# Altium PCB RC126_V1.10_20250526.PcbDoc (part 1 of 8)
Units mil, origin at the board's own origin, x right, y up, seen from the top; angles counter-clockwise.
Board outline 6299.62 x 3544.12 mil, 4 copper layers (Top, GND, Power, Bottom), stack 35.4 mil thick; 509 components, 417 nets, 1867 pads, 2150 vias.
Unrouted connection lines stored in the file: 1451.
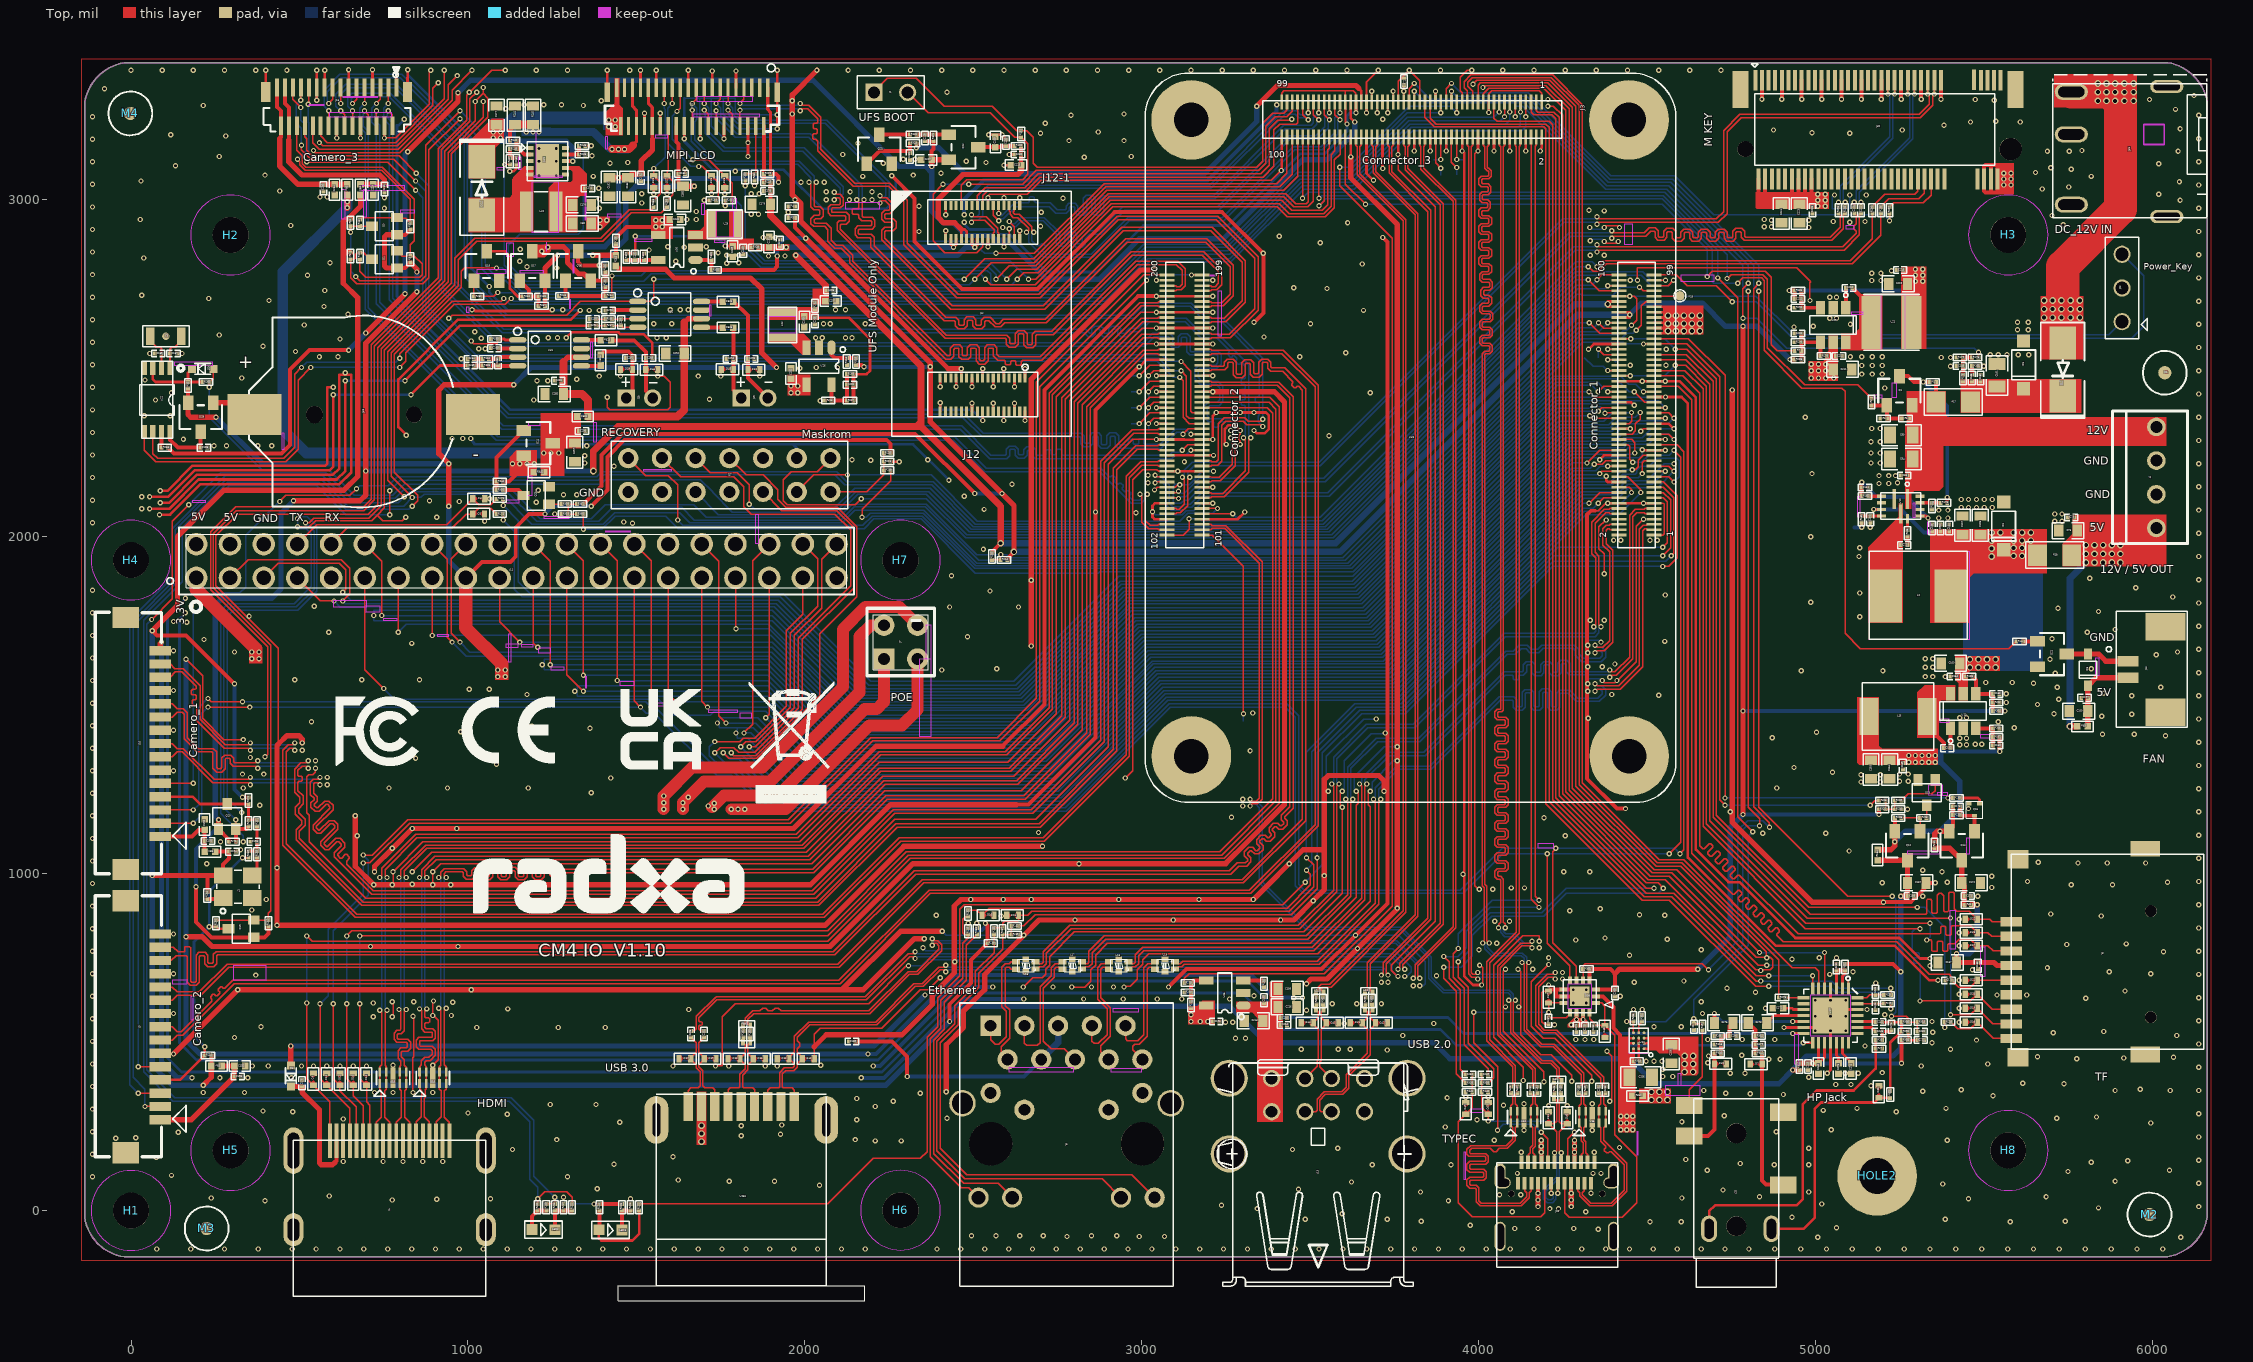
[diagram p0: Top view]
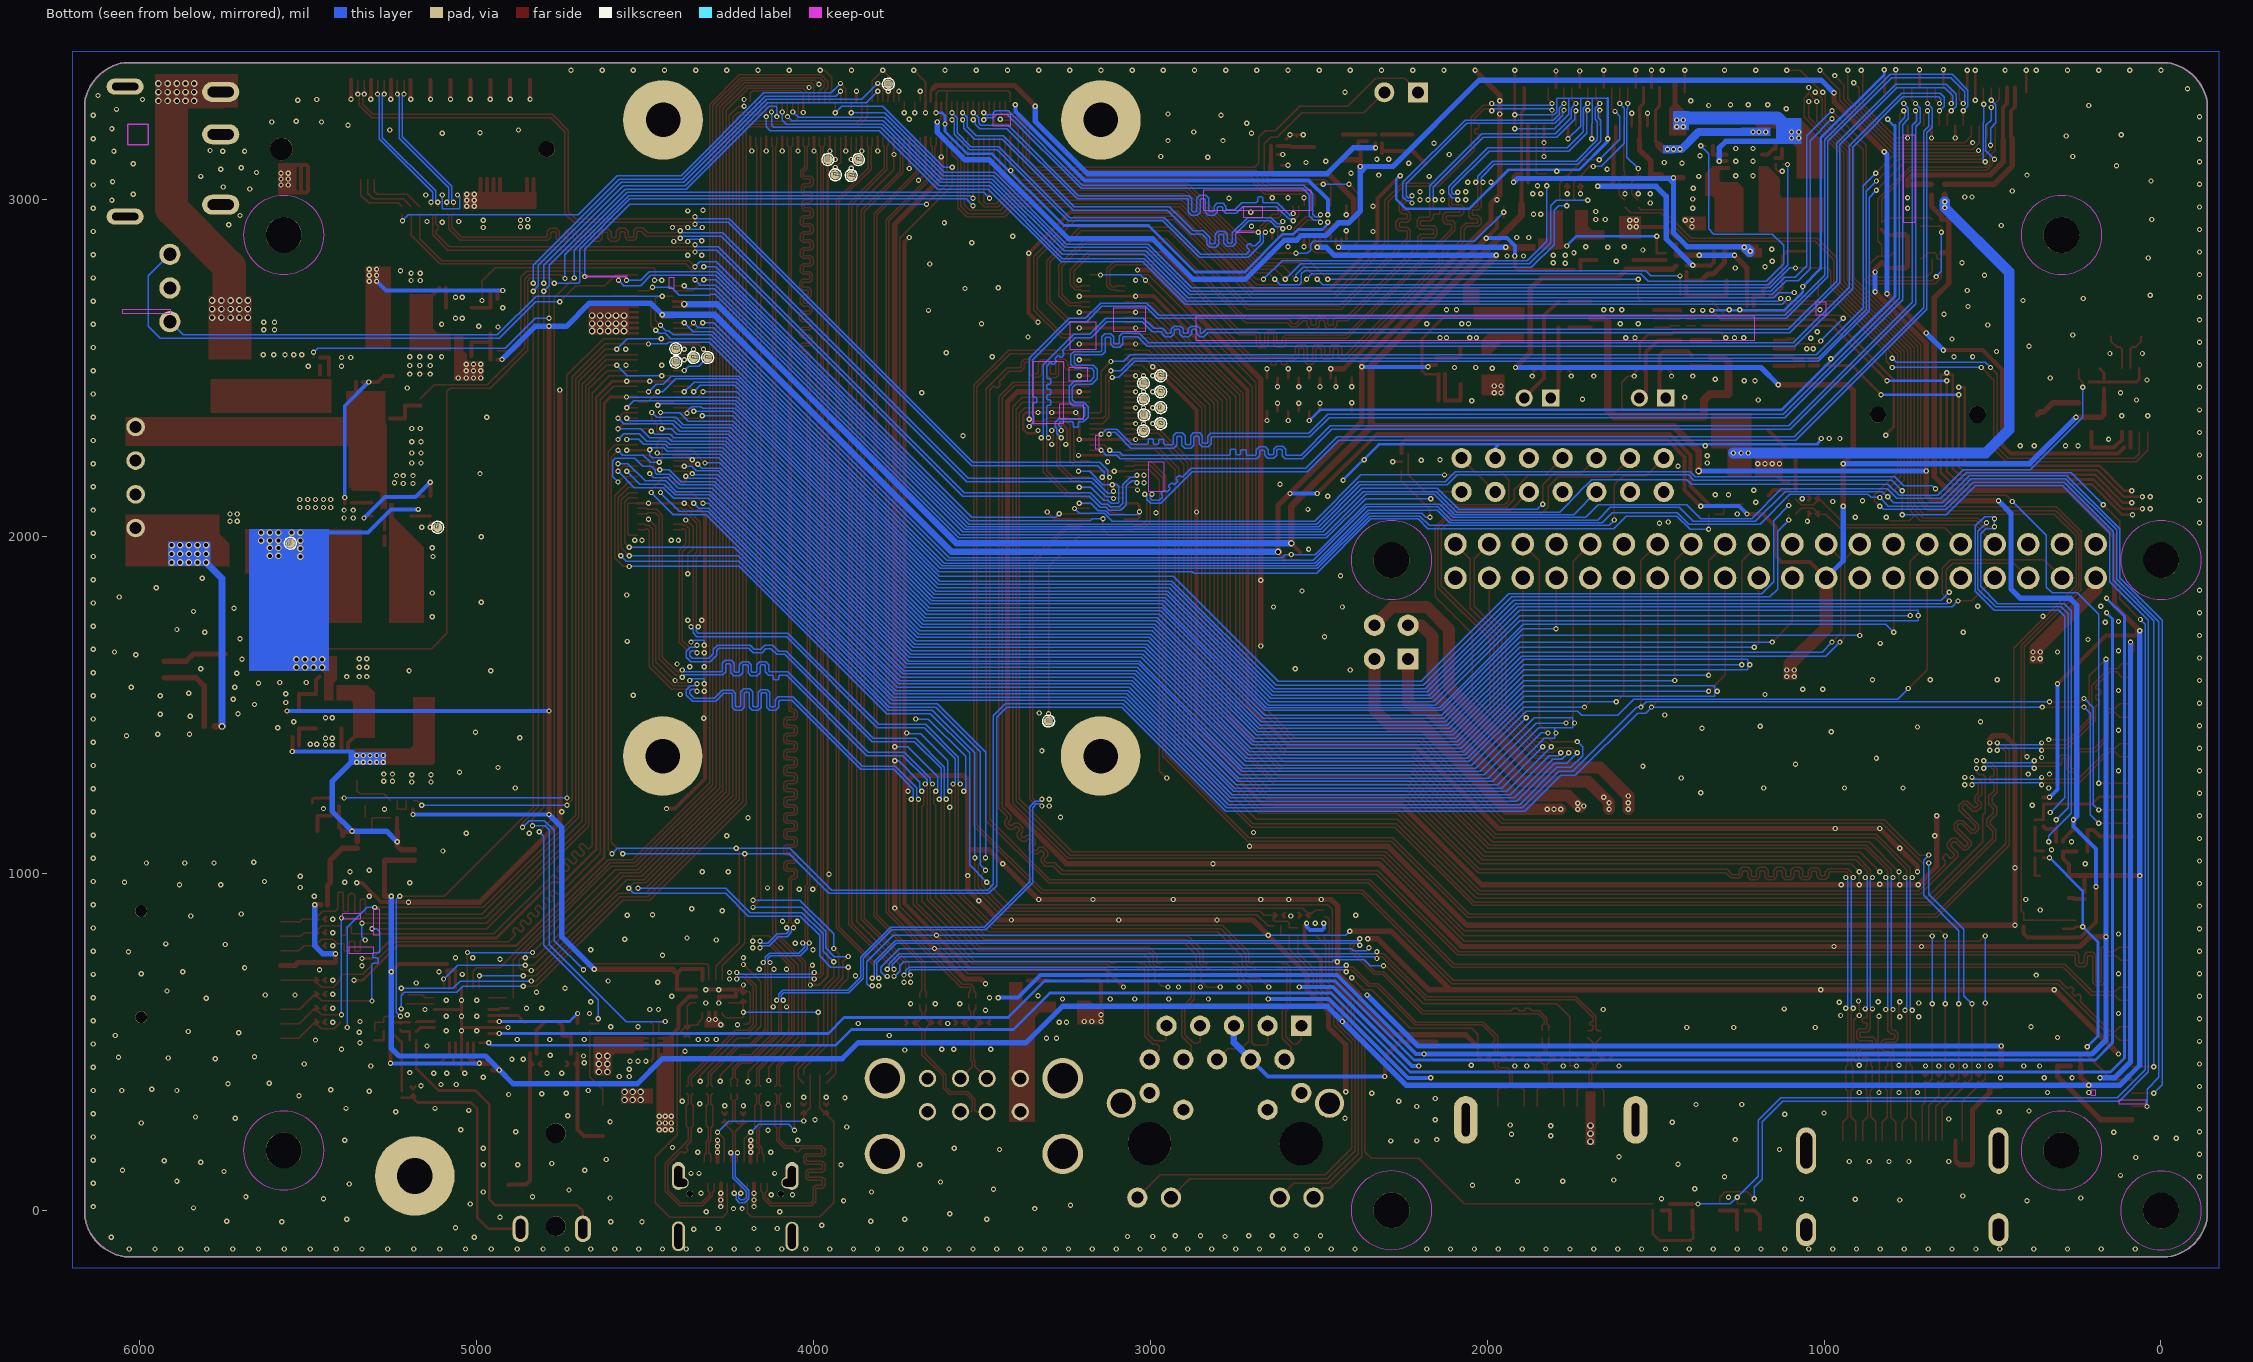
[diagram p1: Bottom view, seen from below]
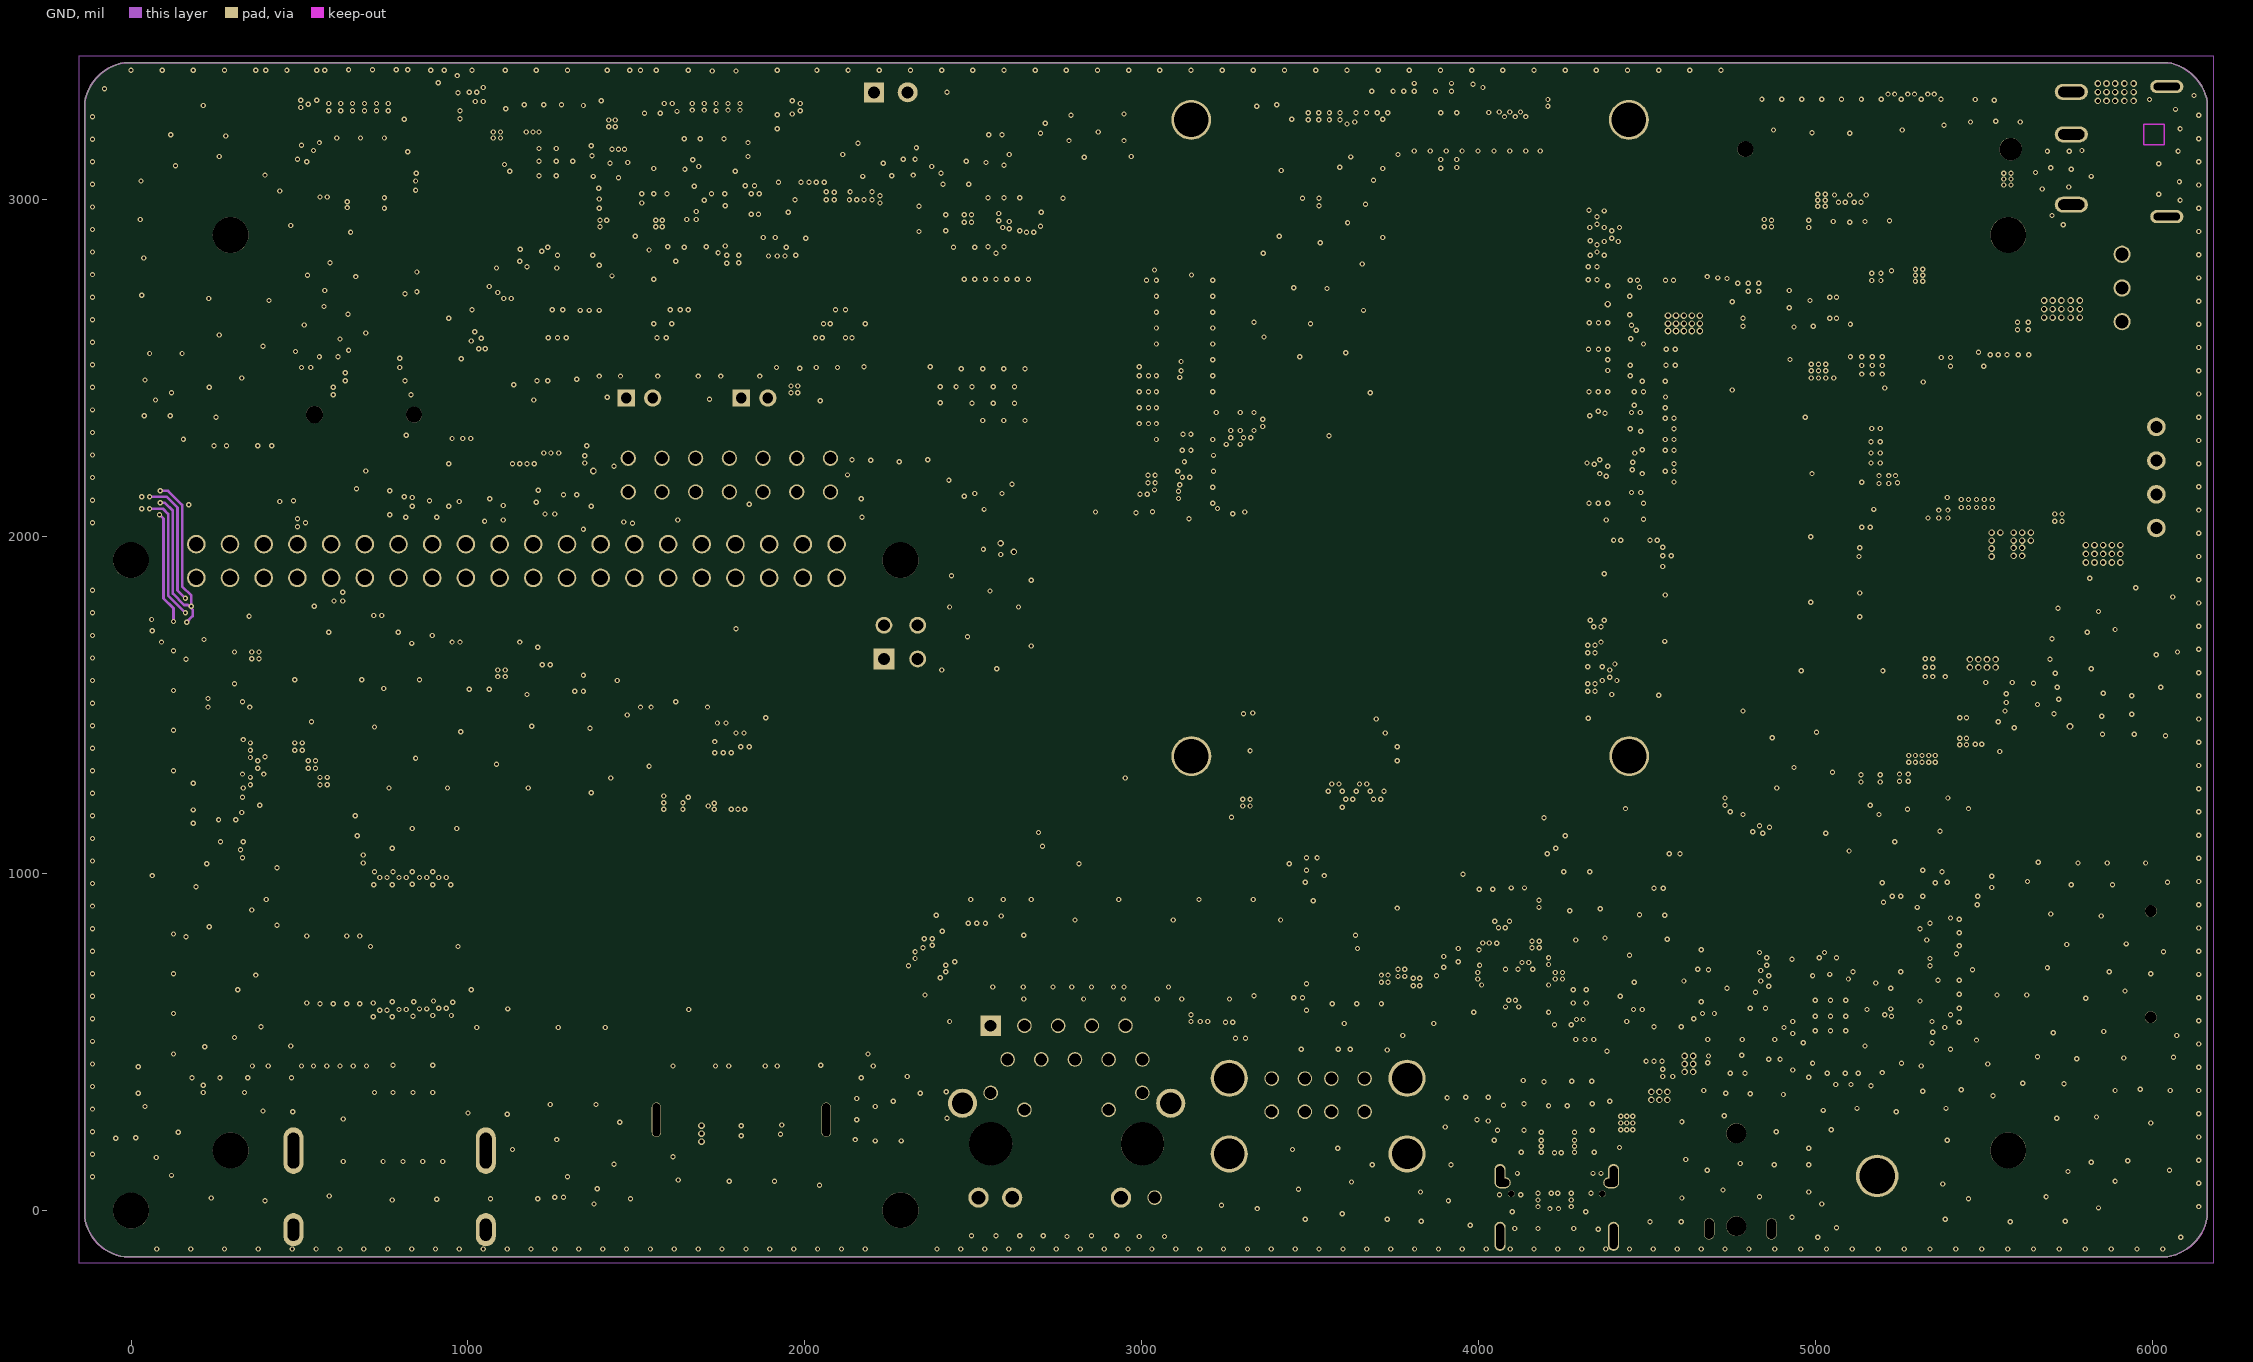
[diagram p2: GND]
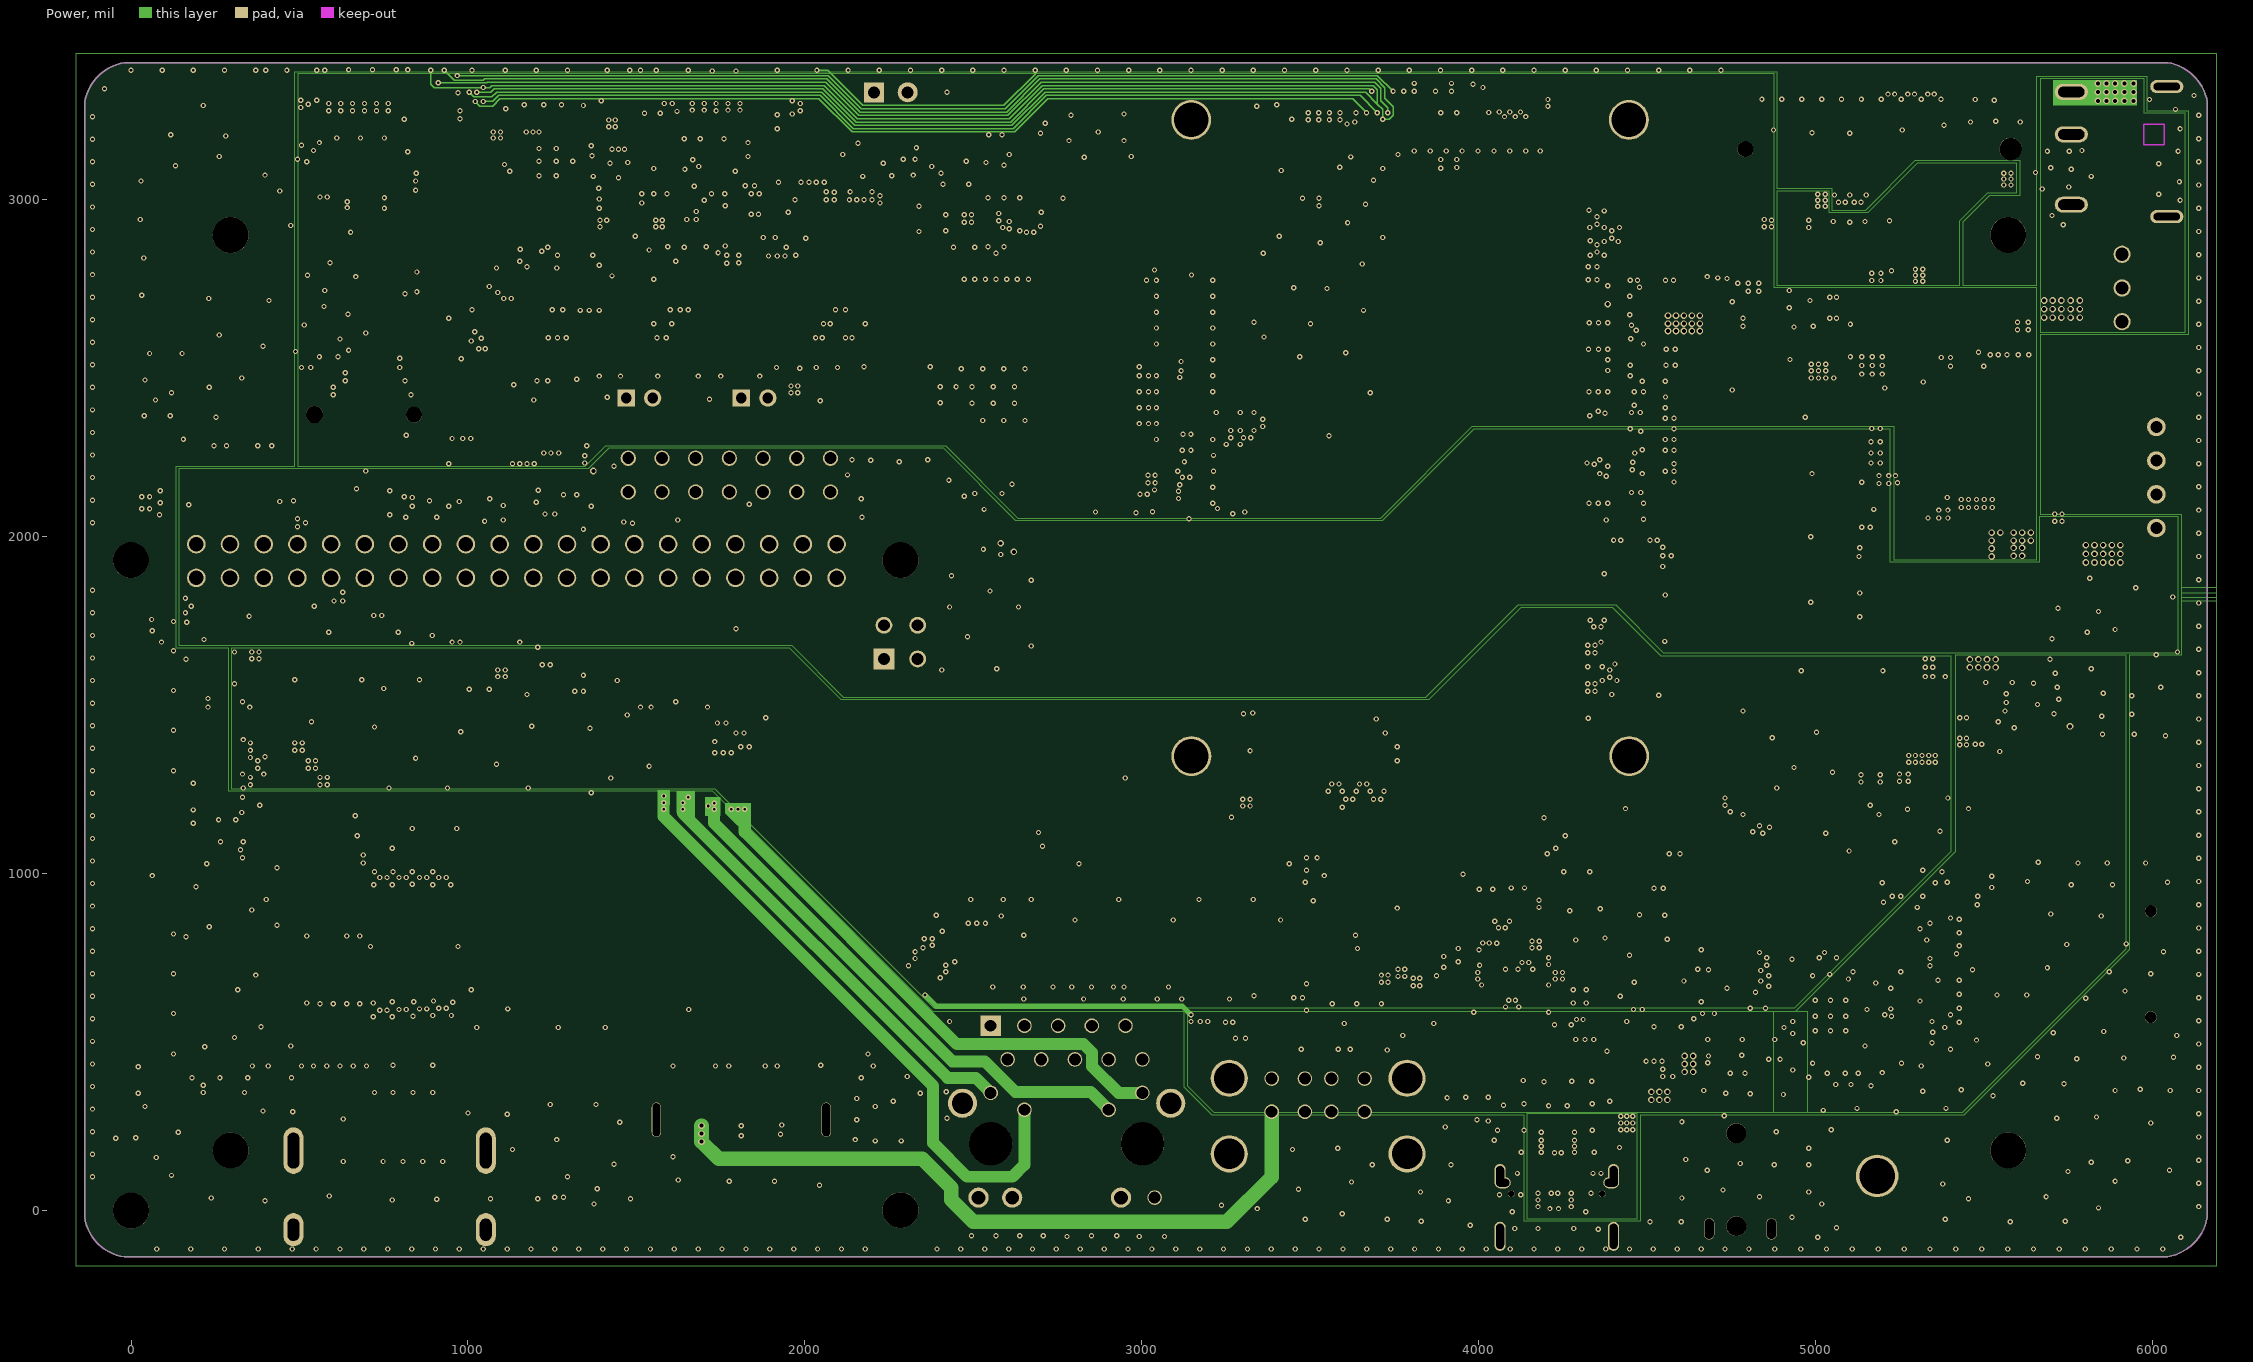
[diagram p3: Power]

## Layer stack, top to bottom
Solder Mask Top: solder mask 0.4, Solder Resist, Dk 3.5
Top: signal copper 1.35
Dielectric 1: dielectric 10, FR-4, Dk 4.3
GND: signal copper 1.35
Dielectric2: dielectric 10, FR-4, Dk 4.3
Power: signal copper 1.35
Dielectric3: dielectric 10, FR-4, Dk 4.3
Bottom: signal copper 1.35
Solder Mask Bottom: solder mask 0.4, Solder Resist, Dk 3.5

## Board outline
-137.8,3288.58 -137.79,3288.63 cw(c4.92,3263.98) -19.69,3406.69 6043.7,3406.69 6043.62,3406.71 cw(c6020.78,3265.66) 6161.81,3288.58 6161.81,-19.29 6161.82,-19.26 cw(c6017.43,6.98) 6043.7,-137.4 -19.69,-137.4 -19.63,-137.41 cw(c-0.02,0.38) -137.8,-19.29

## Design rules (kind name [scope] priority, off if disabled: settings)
Clearance "Clearance - Default - DEFAULT - Via" [IsVia vs IsVia] p1: gap=0 ignorepadtopadclearanceinfootprint=FALSE
Clearance "Clearance - Default - DEFAULT- SMD" [IsVia vs IsSMTPin] p2: gap=0 ignorepadtopadclearanceinfootprint=FALSE
Clearance "Clearance - Default - DEFAULT - Net" [All] p3: gap=3.94 ignorepadtopadclearanceinfootprint=FALSE except(7.87: Arc-Fill Arc-Poly Arc-Region Track-Fill Track-Poly Track-Region SMDPad-Fill SMDPad-Poly SMDPad-Region THPad-Fill THPad-Poly THPad-Region Via-Fill Via-Poly Via-Region Fill-Fill Fill-Poly Fill-Region Poly-Poly Poly-Region Region-Region; 10: Arc-Hole Track-Hole SMDPad-Hole THPad-Hole Via-Hole Fill-Hole Poly-Hole Region-Hole Text-Text Text-Hole)
ComponentClearance "ComponentClearance - Default - DEFAULT" [All] p1: gap=0 collisioncheckmode=3 verticalgap=10 showdistances=FALSE
DiffPairsRouting "DiffPairsRouting - DiffPair - SSTX2" [InDifferentialPairClass('DiffPairClassFor_DP_GAP_39370_Width_39370')] p1: maxlimit=3.94 minlimit=3.94 mostfreqgap=3.94 toplayer_minwidth=3.94 toplayer_maxwidth=3.94 toplayer_prefwidth=3.94 midlayer1_minwidth=3.94 midlayer1_maxwidth=3.94 midlayer1_prefwidth=3.94 midlayer2_minwidth=3.94 midlayer2_maxwidth=3.94 midlayer2_prefwidth=3.94 bottomlayer_minwidth=3.94 bottomlayer_maxwidth=3.94 bottomlayer_prefwidth=3.94 maxuncoupledlength=500
DiffPairsRouting "DiffPairsRouting - DiffPair - Default" [All] p2: maxlimit=5.91 minlimit=5.91 mostfreqgap=5.91 toplayer_minwidth=3.94 toplayer_maxwidth=3.94 toplayer_prefwidth=3.94 midlayer1_minwidth=3.94 midlayer1_maxwidth=3.94 midlayer1_prefwidth=3.94 midlayer2_minwidth=3.94 midlayer2_maxwidth=3.94 midlayer2_prefwidth=3.94 bottomlayer_minwidth=3.94 bottomlayer_maxwidth=3.94 bottomlayer_prefwidth=3.94 maxuncoupledlength=500
FanoutControl Fanout_SOIC [IsSOIC] p1: bgadir=Out bgaviamode=Centered fanoutstyle=Auto fanoutdirection=Alternating viagrid=1 // Fanout_SOIC (Default Rule)
FanoutControl Fanout_Small [(CompPinCount < 5)] p2: bgadir=Out bgaviamode=Centered fanoutstyle=Auto fanoutdirection=OutThenIn viagrid=1 // Fanout_Small (Default Rule)
FanoutControl Fanout_LCC [IsLCC] p3: bgadir=Out bgaviamode=Centered fanoutstyle=Auto fanoutdirection=Alternating viagrid=1 // Fanout_LCC (Default Rule)
FanoutControl Fanout_BGA [IsBGA] p4: bgadir=Out bgaviamode=Centered fanoutstyle=Auto fanoutdirection=Alternating viagrid=1 // Fanout_BGA (Default Rule)
HoleToHoleClearance "HoleToHoleClearance - Default - DEFAULT" [All] p1: gap=0 allowstackedmicrovias=TRUE
Length "Length - DiffPair - Default" [InAnyDifferentialPair] p1: maxlimit=18503.27 minlimit=0
Length "Length - NetClass - HighSpeedClass_4(RuleSet)" [InNetClass('HighSpeedClass_4(RuleSet)')] p2: maxlimit=18503.27 minlimit=0
Length "Length - NetClass - MLNetGroup16" [InNetClass('MLNetGroup16')] p3: maxlimit=18503.27 minlimit=0
Length "Length - NetClass - MLNetGroup11" [InNetClass('MLNetGroup11')] p4: maxlimit=18503.27 minlimit=0
Length "Length - NetClass - MLNetGroup14" [InNetClass('MLNetGroup14')] p5: maxlimit=18503.27 minlimit=0
Length "Length - NetClass - MLNetGroup1" [InNetClass('MLNetGroup1')] p6: maxlimit=18503.27 minlimit=0
Length "Length - NetClass - MLNetGroup15" [InNetClass('MLNetGroup15')] p7: maxlimit=18503.27 minlimit=0
Length "Length - NetClass - MLNetGroup12" [InNetClass('MLNetGroup12')] p8: maxlimit=18503.27 minlimit=0
Length "Length - NetClass - MLNetGroup10" [InNetClass('MLNetGroup10')] p9: maxlimit=18503.27 minlimit=0
Length "Length - NetClass - MLNetGroup13" [InNetClass('MLNetGroup13')] p10: maxlimit=18503.27 minlimit=0
Length "Default Length_1" [All] p11: maxlimit=50000 minlimit=0
Length "Default Length" [All] p12: maxlimit=18503.27 minlimit=0
MatchedLengths "MatchedLengths - DiffPair - Default" [InAnyDifferentialPair] p1: tolerance=19.68 checknetsindiffpair=TRUE checkdiffpairvsdiffpair=FALSE checkxsignals=FALSE checkothers=FALSE
MatchedLengths "MatchedLengths - NetClass - HighSpeedClass_4(RuleSet)" [InNetClass('HighSpeedClass_4(RuleSet)')] p2: tolerance=19.68 checknetsindiffpair=FALSE checkdiffpairvsdiffpair=TRUE checkxsignals=TRUE checkothers=TRUE
MatchedLengths "MatchedLengths - NetClass - MLNetGroup11" [InNetClass('MLNetGroup11')] p3: tolerance=19.68 checknetsindiffpair=FALSE checkdiffpairvsdiffpair=TRUE checkxsignals=TRUE checkothers=TRUE
MatchedLengths "MatchedLengths - NetClass - MLNetGroup16" [InNetClass('MLNetGroup16')] p4: tolerance=19.68 checknetsindiffpair=FALSE checkdiffpairvsdiffpair=TRUE checkxsignals=TRUE checkothers=TRUE
MatchedLengths "MatchedLengths - NetClass - MLNetGroup14" [InNetClass('MLNetGroup14')] p5: tolerance=19.68 checknetsindiffpair=FALSE checkdiffpairvsdiffpair=TRUE checkxsignals=TRUE checkothers=TRUE
MatchedLengths "MatchedLengths - NetClass - MLNetGroup1" [InNetClass('MLNetGroup1')] p6: tolerance=19.68 checknetsindiffpair=FALSE checkdiffpairvsdiffpair=TRUE checkxsignals=TRUE checkothers=TRUE
MatchedLengths "MatchedLengths - NetClass - MLNetGroup15" [InNetClass('MLNetGroup15')] p7: tolerance=19.68 checknetsindiffpair=FALSE checkdiffpairvsdiffpair=TRUE checkxsignals=TRUE checkothers=TRUE
MatchedLengths "MatchedLengths - NetClass - MLNetGroup13" [InNetClass('MLNetGroup13')] p8: tolerance=19.68 checknetsindiffpair=FALSE checkdiffpairvsdiffpair=TRUE checkxsignals=TRUE checkothers=TRUE
MatchedLengths "MatchedLengths - NetClass - MLNetGroup12" [InNetClass('MLNetGroup12')] p9: tolerance=19.68 checknetsindiffpair=FALSE checkdiffpairvsdiffpair=TRUE checkxsignals=TRUE checkothers=TRUE
MatchedLengths "MatchedLengths - NetClass - MLNetGroup10" [InNetClass('MLNetGroup10')] p10: tolerance=19.68 checknetsindiffpair=FALSE checkdiffpairvsdiffpair=TRUE checkxsignals=TRUE checkothers=TRUE
MatchedLengths "Default Matched Lengths" [All] p11: tolerance=19.68 checknetsindiffpair=FALSE checkdiffpairvsdiffpair=TRUE checkxsignals=TRUE checkothers=TRUE
MaxMinImpedance "Default Impedance" [All] p1: minimum=50.00 maximum=150.0
MaxMinImpedance "Default Impedance_1" [All] p2: minimum=50.00 maximum=150.0
ParallelSegment "Default Parallel Segment Same Layer_1" [All] p1: limit=1000 gap=200
ParallelSegment "Default Parallel Segment Adjasent_1" [All] p2: limit=1000 gap=200
ParallelSegment "Default Parallel Segment Same Layer" [All] p3: limit=1000 gap=200
ParallelSegment "Default Parallel Segment Adjasent" [All] p4: limit=1000 gap=200
PlaneClearance "PlaneClearance - FootPrint 'CON_TH20X2_2D54_STA'" [HasFootprint('CON_TH20X2_2D54_STA')] p1: clearance=7.87 // PAD - Power Plane Clearance
PlaneClearance "PlaneClearance - FootPrint 'CONM_TH2X2_2D54_STA'" [HasFootprint('CONM_TH2X2_2D54_STA')] p2: clearance=7.5 // PAD - Power Plane Clearance
PlaneClearance "PlaneClearance - FootPrint 'M2-M_KEY_SM_75_0D5'" [HasFootprint('M2-M_KEY_SM_75_0D5')] p3: clearance=0 // PAD - Power Plane Clearance
PlaneClearance "PlaneClearance - FootPrint 'CONM_TH2X7_2D54_STA'" [HasFootprint('CONM_TH2X7_2D54_STA')] p4: clearance=4.92 // PAD - Power Plane Clearance
PlaneConnect "Default PlaneConnect" [All] p1: planeconnectstyle=Relief reliefexpansion=20 reliefentries=4 reliefconductorwidth=15 reliefairgap=10
PolygonConnect "PolygonConnect - Default SMT" [IsSMTPin] p1: connectstyle=Direct reliefconductorwidth=10 reliefentries=4 polygonreliefangle="45 Angle" airgapwidth=10
PolygonConnect "PolygonConnect - Default Pad" [All] p2: connectstyle=Relief reliefconductorwidth=15 reliefentries=4 polygonreliefangle="45 Angle" airgapwidth=10
RoutingLayers "RoutingLayers - Default - DEFAULT" [All] p1: top layer_v5=TRUE mid layer 1_v5=TRUE mid layer 2_v5=TRUE bottom layer_v5=TRUE
RoutingPriority "RoutingPriority - Default - DEFAULT" [All] p1: routingpriority=3
RoutingTopology "Default Routing Topology" [All] p1: topology=Shortest
RoutingVias "RoutingVias - Default - DEFAULT" [All] p1: holewidth=7.87 width=15.75 viastyle="Through Hole" minholewidth=7.87 minwidth=15.75 maxholewidth=7.87 maxwidth=15.75
SMDToCorner "SMDToCorner - Default - DEFAULT" [All] p1: distance=0
SolderMaskExpansion [All] p1: expansion=4 istentingtop=FALSE
Width "Default Width" [All] p1: maxlimit=196.85 minlimit=3.94 preferedwidth=3.94
18 further rules are at their usual default settings.

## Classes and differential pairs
net class MLNetGroup3: DP_TX_AUXN_SBU2 DP_TX_AUXP_SBU1 SSRX1N_DP_TX_D0N SSRX1P_DP_TX_D0P SSRX2N_DP_TX_D2N SSRX2P_DP_TX_D2P SSTX1N_DP_TX_D1N SSTX1P_DP_TX_D1P SSTX2N_DP_TX_D3N SSTX2P_DP_TX_D3P
net class MLNetGroup2: PHY1_MDI0+ PHY1_MDI0- PHY1_MDI1+ PHY1_MDI1- PHY1_MDI2+ PHY1_MDI2- PHY1_MDI3+ PHY1_MDI3-
net class MLNetGroup12: MIPI_DPHY_CSI3_RX_CLKN MIPI_DPHY_CSI3_RX_CLKP MIPI_DPHY_CSI3_RX_D0N MIPI_DPHY_CSI3_RX_D0P MIPI_DPHY_CSI3_RX_D1N MIPI_DPHY_CSI3_RX_D1P
net class MLNetGroup13: MIPI_DPHY_CSI4_RX_CLKN MIPI_DPHY_CSI4_RX_CLKP MIPI_DPHY_CSI4_RX_D0N MIPI_DPHY_CSI4_RX_D0P MIPI_DPHY_CSI4_RX_D1N MIPI_DPHY_CSI4_RX_D1P
net class MLNetGroup10: UFS_RX_D0N UFS_RX_D0P UFS_RX_D1N UFS_RX_D1P UFS_TX_D0N UFS_TX_D0P UFS_TX_D1N UFS_TX_D1P
net class MLNetGroup11: MIPI_DPHY_CSI2_RX_CLKN MIPI_DPHY_CSI2_RX_CLKP MIPI_DPHY_CSI2_RX_D0N MIPI_DPHY_CSI2_RX_D0P MIPI_DPHY_CSI2_RX_D1N MIPI_DPHY_CSI2_RX_D1P
net class MLNetGroup16: HDMI_TX0N HDMI_TX0P HDMI_TX1N HDMI_TX1P HDMI_TX2N HDMI_TX2P HDMI_TX3N HDMI_TX3P
net class HighSpeedClass_4(RuleSet): PHY1_MDI0+ PHY1_MDI1+ PHY1_MDI2+ PHY1_MDI3+
net class MLNetGroup14: MIPI_DPHY_DSI_TX_CLKN MIPI_DPHY_DSI_TX_CLKP MIPI_DPHY_DSI_TX_D0N MIPI_DPHY_DSI_TX_D0P MIPI_DPHY_DSI_TX_D1N MIPI_DPHY_DSI_TX_D1P MIPI_DPHY_DSI_TX_D2N MIPI_DPHY_DSI_TX_D2P MIPI_DPHY_DSI_TX_D3N MIPI_DPHY_DSI_TX_D3P
net class MLNetGroup15: MIPI_DPHY_CSI1_RX_CLKN MIPI_DPHY_CSI1_RX_CLKP MIPI_DPHY_CSI1_RX_D0N MIPI_DPHY_CSI1_RX_D0P MIPI_DPHY_CSI1_RX_D1N MIPI_DPHY_CSI1_RX_D1P
net class MLNetGroup1: SDMMC0_CLK SDMMC0_CMD SDMMC0_D0 SDMMC0_D1 SDMMC0_D2/JTAG_TCK_M0 SDMMC0_D3/JTAG_TMS_M0
differential pair class DiffPairClassFor_DP_GAP_39370_Width_39370: DP_TX_AUX N381984 N384347 N384523 N3819842 PCIE1_RX PCIE1_TX SSRX1 SSRX2 SSTX1 SSTX2 TYPEC0_OTGD TYPEC0RX1 TYPEC0RX2 TYPEC0TX1 TYPEC0TX2 USB2_OTG0_D USB20_1D USB20_2D USB20_3D
differential pair MIPI_DPHY_CSI1_RX_CLK: +MIPI_DPHY_CSI1_RX_CLKN -MIPI_DPHY_CSI1_RX_CLKP
differential pair MIPI_DPHY_CSI1_RX_D0: +MIPI_DPHY_CSI1_RX_D0N -MIPI_DPHY_CSI1_RX_D0P
differential pair MIPI_DPHY_CSI1_RX_D1: +MIPI_DPHY_CSI1_RX_D1N -MIPI_DPHY_CSI1_RX_D1P
differential pair MIPI_DPHY_CSI4_RX_D1: +MIPI_DPHY_CSI4_RX_D1N -MIPI_DPHY_CSI4_RX_D1P
differential pair N1946387: +N19463875 -N19463877
differential pair MIPI_DPHY_CSI4_RX_CLK: +MIPI_DPHY_CSI4_RX_CLKP -MIPI_DPHY_CSI4_RX_CLKN
differential pair MIPI_DPHY_CSI4_RX_D0: +MIPI_DPHY_CSI4_RX_D0P -MIPI_DPHY_CSI4_RX_D0N
differential pair MIPI_DPHY_CSI3_RX_D0: +MIPI_DPHY_CSI3_RX_D0N -MIPI_DPHY_CSI3_RX_D0P
differential pair MIPI_DPHY_CSI3_RX_D1: +MIPI_DPHY_CSI3_RX_D1N -MIPI_DPHY_CSI3_RX_D1P
differential pair N384347: +N38434760 -N38434788
differential pair MIPI_DPHY_CSI3_RX_CLK: +MIPI_DPHY_CSI3_RX_CLKP -MIPI_DPHY_CSI3_RX_CLKN
differential pair MIPI_DPHY_CSI2_RX_CLK: +MIPI_DPHY_CSI2_RX_CLKP -MIPI_DPHY_CSI2_RX_CLKN
differential pair MIPI_DPHY_CSI2_RX_D0: +MIPI_DPHY_CSI2_RX_D0N -MIPI_DPHY_CSI2_RX_D0P
differential pair MIPI_DPHY_CSI2_RX_D1: +MIPI_DPHY_CSI2_RX_D1N -MIPI_DPHY_CSI2_RX_D1P
differential pair N19471: +N19471161 -N19471204
differential pair PHY_MDI0: +PHY_MDI0- -PHY_MDI0+
differential pair PHY_MDI1: +PHY_MDI1- -PHY_MDI1+
differential pair PHY_MDI2: +PHY_MDI2- -PHY_MDI2+
differential pair PHY1_MDI2: +PHY1_MDI2- -PHY1_MDI2+
differential pair PHY1_MDI0: +PHY1_MDI0+ -PHY1_MDI0-
differential pair PHY1_MDI1: +PHY1_MDI1- -PHY1_MDI1+
differential pair PHY1_MDI3: +PHY1_MDI3- -PHY1_MDI3+
differential pair UFS_RX_D0: +UFS_RX_D0P -UFS_RX_D0N
differential pair N381984: +N38198493 -N38198421
differential pair N3819842: +N38198427 -N38198429
differential pair UFS_RX_D1: +UFS_RX_D1P -UFS_RX_D1N
differential pair PHY_MDI3: +PHY_MDI3- -PHY_MDI3+
differential pair UFS_TX_D1: +UFS_TX_D1P -UFS_TX_D1N
differential pair UFS_TX_D0: +UFS_TX_D0P -UFS_TX_D0N
differential pair HDMI_TX1: +HDMI_TX1N -HDMI_TX1P
differential pair HDMI_TX2: +HDMI_TX2N -HDMI_TX2P
differential pair MIPI_DPHY_DSI_TX_D3: +MIPI_DPHY_DSI_TX_D3P -MIPI_DPHY_DSI_TX_D3N
differential pair HDMI_TX0: +HDMI_TX0N -HDMI_TX0P
differential pair TYPEC0RX2: +TYPEC0RX2P -TYPEC0RX2N
differential pair TYPEC0RX1: +TYPEC0RX1P -TYPEC0RX1N
differential pair HDMI_TX3: +HDMI_TX3N -HDMI_TX3P
differential pair PCIE0_SOC_RX: +PCIE0_SOC_RXN -PCIE0_SOC_RXP
differential pair PCIE0_SOC_REFCLK: +PCIE0_SOC_REFCLKN -PCIE0_SOC_REFCLKP
differential pair PCIE0_SOC_TX: +PCIE0_SOC_TXP -PCIE0_SOC_TXN
differential pair MIPI_DPHY_DSI_TX_CLK: +MIPI_DPHY_DSI_TX_CLKP -MIPI_DPHY_DSI_TX_CLKN
differential pair MIPI_DPHY_DSI_TX_D2: +MIPI_DPHY_DSI_TX_D2P -MIPI_DPHY_DSI_TX_D2N
differential pair MIPI_DPHY_DSI_TX_D1: +MIPI_DPHY_DSI_TX_D1P -MIPI_DPHY_DSI_TX_D1N
differential pair MIPI_DPHY_DSI_TX_D0: +MIPI_DPHY_DSI_TX_D0P -MIPI_DPHY_DSI_TX_D0N
differential pair TYPEC0TX1: +TYPEC0TX1N -TYPEC0TX1P
differential pair PCIE1_TX: +PCIE1_TXP/USB3_OTG1_SSTXP -PCIE1_TXN/USB3_OTG1_SSTXN
differential pair DP_TX_AUX: +DP_TX_AUXN_SBU2 -DP_TX_AUXP_SBU1
differential pair SSRX1: +SSRX1P_DP_TX_D0P -SSRX1N_DP_TX_D0N
differential pair PCIE1_RX: +PCIE1_RXP/USB3_OTG1_SSRXP -PCIE1_RXN/USB3_OTG1_SSRXN
differential pair N384523: +N38452344 -N38452372
differential pair TYPEC0_OTGD: +TYPEC0_OTGDM -TYPEC0_OTGDP
differential pair USB2_OTG0_D: +USB2_OTG0_DM -USB2_OTG0_DP
differential pair USB20_2D: +USB20_2DP -USB20_2DM
differential pair USB20_1D: +USB20_1DP -USB20_1DM
differential pair TYPEC0TX2: +TYPEC0TX2N -TYPEC0TX2P
differential pair USB20_3D: +USB20_3DP -USB20_3DM
differential pair SSRX2: +SSRX2P_DP_TX_D2P -SSRX2N_DP_TX_D2N
differential pair SSTX1: +SSTX1P_DP_TX_D1P -SSTX1N_DP_TX_D1N
differential pair SSTX2: +SSTX2N_DP_TX_D3N -SSTX2P_DP_TX_D3P

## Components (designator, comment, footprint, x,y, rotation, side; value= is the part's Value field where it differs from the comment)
C1 "C0201" C0201 4637.8,545.28 r270 top
C77 "C0201" C0201 5261.81,1974.41 r180 top
C78 "C0603" C0603 5748.03,2017.72 r180 top
C79 "C0201" C0201 5757.87,2057.09 r180 top
C83 "C0201" C0201 5261.81,2181.1 r180 top
C84 "C0805" C0805 5253.94,2230.32 r180 top
C89 "C0805" C0805 5253.94,2301.18 r180 top
C90 "C0201" C0201 5370.08,2025.59 r90 top
C106 "C0603" C0603 5488.19,2033.46 r90 top
C107 "C0603" C0603 5435.04,2033.46 r90 top
C144 "C0201" C0201 5395.67,2025.59 r90 top
C146 "C0201" C0201 5344.49,2025.59 r90 top
C148 "C0201" C0201 5427.17,2505.91 r180 top
C150 "C0201" C0201 5161.42,2051.18 r270 top
C151 "C0201" C0201 5145.67,2145.67 r0 top
C152 "C0201" C0201 5389.76,1372.05 r180 top
C153 "C0603" C0603 5399.61,1624.02 r180 top
C154 "C0201" C0201 5409.45,1584.65 r180 top
C155 "C0201" C0201 5462.6,2470.47 r90 top
C156 "C0603" C0603 5163.39,1309.06 r270 top
C157 "C0603" C0603 5299.21,972.44 r0 top
C158 "C0201" C0201 5281.5,933.07 r0 top
C159 "C0201" C0201 5257.87,1318.9 r270 top
C160 "C0201" C0201 5535.43,1379.92 r180 top
C161 "C0805" C0805 5537.4,2478.35 r270 top
C162 "C0201" C0201 5488.19,2470.47 r90 top
C163 "C0201" C0201 5535.43,1533.46 r0 top
C164 "C0603" C0603 5218.5,1309.06 r270 top
C167 "C0603" C0603 5389.76,736.22 r180 top
C168 "C0201" C0201 5480.32,726.38 r270 top
C169 "C0201" C0201 2139.76,501.97 r0 top
C170 "C0201" C0201 5393.7,683.07 r180 top
C171 "C0201" C0201 5450.79,933.07 r0 top
C172 "C0603" C0603 5460.63,972.44 r0 top
C173 "C0201" C0201 5417.32,1198.82 r0 top
C174 "C0201" C0201 1356.3,3033.46 r0 top
C175 "C0201" C0201 507.87,377.95 r90 top
C176 "C0603" C0603 1338.58,2984.25 r0 top
C177 "C0603" C0603 1084.65,3250 r90 top
C178 "C0201" C0201 1887.8,3025.59 r180 top
C179 "C0603" C0603 1870.08,2986.22 r180 top
C180 "C0201" C0201 1143.7,3114.17 r90 top
C181 "C0201" C0201 1218.5,2712.6 r180 top
C182 "C0603" C0603 1419.29,3037.4 r270 top
C183 "C0603" C0603 1474.41,3037.4 r270 top
C184 "C0201" C0201 1513.78,3064.96 r270 top
C185 "C0603" C0603 1637.8,3011.81 r270 top
C186 "C0201" C0201 1633.86,3076.77 r0 top
C187 "C0201" C0201 125.98,2543.31 r180 top
C188 "C0201" C0201 216.54,2263.78 r0 top
C189 "C0201" C0201 80.71,2543.31 r0 top
C190 "C0402" C0402 218.5,1145.67 r90 top
C191 "C0201" C0201 228.35,1096.46 r0 top
C192 "C0402" C0402 322.83,429.13 r0 top
C193 "C0201" C0201 316.93,397.64 r0 top
C194 "C0201" C0201 301.18,1064.96 r0 top
C195 "C0201" C0201 364.17,1094.49 r180 top
C196 "C0201" C0201 3220.47,561.02 r0 top
C197 "C0201" C0201 5797.24,1521.65 r180 top
C198 "C0603" C0603 3431.1,657.48 r0 top
C199 "C0201" C0201 3362.2,624.02 r90 top
C200 "C0603" C0603 5779.53,1482.28 r180 top
C201 "C0201" C0201 2133.86,2450.79 r180 top
C202 "C0402" C0402 1958.66,2484.25 r90 top
C203 "C0402" C0402 1998.03,2637.8 r270 top
C204 "C0201" C0201 1700.79,523.62 r270 top
C205 "C0201" C0201 1661.42,523.62 r270 top
C206 "C0201" C0201 2029.53,2639.76 r270 top
C207 "C0402" C0402 2076.77,2698.82 r0 top
C208 "C0201" C0201 2074.8,2730.32 r0 top
C209 "C0402" C0402 2564.96,3171.26 r90 top
C210 "C0201" C0201 5098.43,2738.19 r0 top
C211 "C0603" C0603 5078.74,2496.06 r0 top
C212 "C0201" C0201 5068.9,2535.43 r0 top
C213 "C0603" C0603 3330.71,562.99 r180 top
C214 "C0201" C0201 3421.26,551.18 r0 top
C215 "C0201" C0201 3421.26,570.87 r0 top
C216 "C0603" C0603 3431.1,604.33 r0 top
C217 "C0201" C0201 4946.85,2704.72 r0 top
C218 "C0201" C0201 5250,2791.34 r180 top
C219 "C0603" C0603 5244.09,2750 r180 top
C220 "C0201" C0201 4946.85,2602.36 r180 top
C221 "C0201" C0201 5114.17,2968.5 r90 top
C222 "C0201" C0201 5133.86,2968.5 r90 top
C223 "C0603" C0603 4950.79,2958.66 r270 top
C224 "C0603" C0603 4897.64,2958.66 r270 top
C225 "C0201" C0201 4990.16,2968.5 r270 top
C226 "C0201" C0201 2596.46,3169.29 r90 top
C227 "C0402" C0402 2360.24,3118.11 r180 top
C228 "C0201" C0201 2356.3,3183.07 r90 top
C229 "C0402" C0402 2625.98,3102.36 r180 top
C230 "C0201" C0201 2631.89,3133.86 r180 top
C231 "C0201" C0201 751.97,3031.5 r270 top
C232 "C0201" C0201 2311.02,3127.95 r270 top
C233 "C0402" C0402 718.5,3029.53 r270 top
C234 "C0402" C0402 604.33,3029.53 r270 top
C235 "C0201" C0201 570.87,3033.46 r270 top
C236 "C0201" C0201 5061.02,722.44 r90 top
C237 "C0402" C0402 1893.7,2874.02 r90 top
C238 "C0201" C0201 1925.2,2872.05 r90 top
C239 "C0402" C0402 1785.43,2846.46 r270 top
C240 "C0201" C0201 1816.93,2848.43 r270 top
C241 "C0402" C0402 1614.17,2940.94 r0 top
C242 "C0201" C0201 1496.06,2830.71 r270 top
C243 "C0201" C0201 4976.38,427.17 r270 top
C244 "C0402" C0402 5007.87,421.26 r270 top
C245 "C0201" C0201 5177.17,649.61 r90 top
C246 "C0201" C0201 5177.17,604.33 r270 top
C247 "C0201" C0201 5187.01,559.06 r0 top
C248 "C0201" C0201 5187.01,531.5 r0 top
C249 "C0201" C0201 4017.72,403.54 r180 top
C250 "C0201" C0201 3970.47,403.54 r0 top
C251 "C0201" C0201 4173.23,358.27 r270 top
C252 "C0201" C0201 4153.54,358.27 r270 top
C253 "C0201" C0201 4375.98,358.27 r270 top
C254 "C0201" C0201 4356.3,358.27 r270 top
C255 "C0603" C0603 4570.87,464.57 r270 top
C256 "C0805" C0805 4480.32,395.67 r0 top
C257 "C0201" C0201 4206.69,562.99 r270 top
C258 "C0201" C0201 4340.55,539.37 r270 top
C269 "C0201" C0201 4403.54,645.67 r270 top
C270 "C0201" C0201 4314.96,539.37 r270 top
C271 "C0201" C0201 4289.37,539.37 r270 top
C272 "C0402" C0402 4887.8,600.39 r180 top
C273 "C0402" C0402 5066.93,421.26 r270 top
C274 "C0402" C0402 5104.33,421.26 r270 top
C275 "C0603" C0603 4726.38,557.09 r0 top
C276 "C0201" C0201 5224.41,545.28 r270 top
C277 "C0201" C0201 5311.02,505.91 r0 top
C278 "C0603" C0603 4826.77,557.09 r180 top
C279 "C0201" C0201 4830.71,492.13 r0 top
C280 "C0201" C0201 4753.94,517.72 r0 top
C281 "C0201" C0201 5311.02,531.5 r0 top
C282 "C0201" C0201 1267.72,2462.6 r180 top
C283 "C0201" C0201 1078.74,2559.06 r0 top
C284 "C0201" C0201 1007.87,2527.56 r0 top
C285 "C0603" C0603 1255.91,2423.23 r180 top
C286 "C0201" C0201 1088.58,2517.72 r270 top
C287 "C0201" C0201 1478.35,2529.53 r180 top
C288 "C0201" C0201 1537.4,2529.53 r0 top
C289 "C0201" C0201 1007.87,2507.87 r0 top
C290 "C0201" C0201 1417.32,2671.26 r0 top
C291 "C0201" C0201 1370.08,2645.67 r0 top
C292 "C0603" C0603 1614.17,2543.31 r180 top
C293 "C0201" C0201 1454.72,2635.83 r270 top
C294 "C0201" C0201 1777.56,2527.56 r180 top
C295 "C0201" C0201 1840.55,2527.56 r0 top
C296 "C0201" C0201 1370.08,2625.98 r0 top
C297 "C0603" C0603 1316.93,2250 r270 top
C298 "C0201" C0201 1338.58,2312.99 r0 top
D1 "SOD_123" SOD_123 5557.09,2031.5 r270 top
D2 "ESD_D0402" ESD_D0402 1031.5,2066.93 r0 top
D3 "ESD_D0402" ESD_D0402 1031.89,2112.6 r0 top
D4 "DO_214AC" DO_214AC 5732.28,2496.06 r270 top
D5 "SOD_123" SOD_123 5616.14,2509.84 r270 top
D6 "SOD_323" SOD_323 5807.09,1604.33 r270 top
D7 "ESD_D0402" ESD_D0402 4822.83,435.04 r180 top
D8 "SOD_523" SOD_523 474.41,399.61 r0 top
D9 "ESD_D0402" ESD_D0402 541.34,389.76 r90 top
D10 "ESD_D0402" ESD_D0402 659.45,389.76 r90 top
D11 "ESD_D0402" ESD_D0402 580.71,389.76 r90 top
D12 "ESD_D0402" ESD_D0402 620.08,389.76 r90 top
D14 "ESD_D0402" ESD_D0402 698.82,389.76 r90 top
D15 "ESD_D0402" ESD_D0402 2616.14,875.98 r180 top
D16 "ESD_D0402" ESD_D0402 2543.31,875.98 r0 top
D17 "ESD_D0402" ESD_D0402 5460.63,785.43 r0 top
D18 "ESD_D0402" ESD_D0402 5460.63,559.06 r0 top
D19 "ESD_D0402" ESD_D0402 5460.63,600.39 r0 top
D20 "ESD_D0402" ESD_D0402 5460.63,641.73 r0 top
D21 "ESD_D0402" ESD_D0402 5460.63,683.07 r0 top
D22 "ESD_D0402" ESD_D0402 5460.63,864.17 r0 top
D23 "ESD_D0402" ESD_D0402 5460.63,824.8 r0 top
D24 "DO_214AC" DO_214AC 1041.34,3033.46 r90 top
D25 "ESD_D0402" ESD_D0402 1722.44,3053.15 r270 top
D26 "ESD_D0402" ESD_D0402 1551.18,3053.15 r270 top
D27 "ESD_D0402" ESD_D0402 1590.55,3053.15 r270 top
D28 "ESD_D0402" ESD_D0402 1761.81,3053.15 r270 top
D29 "SOT_23" SOT_23 206.69,2354.33 r180 top
D30 "SOD_523" SOD_523 212.6,2498.03 r270 top
D31 "ESD_D0402" ESD_D0402 5187.01,352.36 r90 top
D32 "ESD_D0402" ESD_D0402 4716.54,435.04 r0 top
D33 "ESD_D0402" ESD_D0402 1470.47,2496.06 r0 top
D34 "ESD_D0402" ESD_D0402 1545.28,2496.06 r180 top
D35 "ESD_D0402" ESD_D0402 1864.17,450.79 r180 top
D36 "ESD_D0402" ESD_D0402 1935.04,450.79 r0 top
D37 "ESD_D0402" ESD_D0402 1643.7,450.79 r0 top
D38 "ESD_D0402" ESD_D0402 1789.37,450.79 r0 top
D39 "ESD_D0402" ESD_D0402 1718.5,450.79 r180 top
D40 "ESD_D0402" ESD_D0402 2009.84,450.79 r180 top
D41 "ESD_D0402" ESD_D0402 3635.83,557.09 r0 top
D42 "ESD_D0402" ESD_D0402 3710.63,557.09 r180 top
D43 "ESD_D0402" ESD_D0402 3564.96,557.09 r180 top
D44 "ESD_D0402" ESD_D0402 3490.16,557.09 r0 top
D45 "ESD_D0402" ESD_D0402 1769.68,2496.06 r0 top
D46 "ESD_D0402" ESD_D0402 4261.81,275.59 r270 top
D47 "ESD_D0402" ESD_D0402 4206.69,633.86 r270 top
D48 "ESD_D0402" ESD_D0402 4374.02,531.5 r90 top
D49 "ESD_D0402" ESD_D0402 3960.63,303.15 r270 top
D50 "ESD_D0402" ESD_D0402 4027.56,303.15 r270 top
D51 "ESD_D0402" ESD_D0402 4206.69,275.59 r270 top
D52 "ESD_D0402" ESD_D0402 1848.43,2496.06 r180 top
FB1 "FB0402" FB0402 253.94,429.13 r180 top
FB2 "FB0603" FB0603 1338.58,2929.13 r180 top
FB3 "FB0402" FB0402 234.25,1064.96 r0 top
FB4 "FB0402" FB0402 681.1,3029.53 r270 top
FB5 "FB0402" FB0402 641.73,3029.53 r270 top
FB8 "CML_SM4_0D6_1D5" CML_SM4_0D6_1D5 1826.77,523.62 r270 top
FB9 "FB0402" FB0402 5791.34,1437.01 r0 top
FB14 "FB0201" FB0201 5086.61,722.44 r270 top
FB15 "FB0201" FB0201 4950.79,427.17 r90 top
FB16 "FB0201" FB0201 4708.66,466.54 r180 top
FB17 "FB0201" FB0201 4830.71,466.54 r0 top
FB21 "FB0201" FB0201 5220.47,344.49 r270 top
FB22 "FB0402" FB0402 1340.55,2356.3 r0 top
FB23 "FB0402" FB0402 1409.45,2582.68 r0 top
FB24 "FB0402" FB0402 1393.7,2523.62 r90 top
FB25 "FB0402" FB0402 1771.65,2696.85 r0 top
FB26 "FB0402" FB0402 1771.65,2620.08 r0 top
H1 "HOLE_R6_2D7MM" HOLE_R6_2D7MM 0,0 r0 top
H2 "HOLE_R6_2D7MM" HOLE_R6_2D7MM 295.28,2894.88 r0 top
H3 "HOLE_R6_2D7MM" HOLE_R6_2D7MM 5570.87,2895.28 r0 top
H4 "HOLE_R6_2D7MM" HOLE_R6_2D7MM -0.39,1930.32 r0 top
H5 "HOLE_R6_2D7MM" HOLE_R6_2D7MM 295.28,178.35 r0 top
H6 "HOLE_R6_2D7MM" HOLE_R6_2D7MM 2283.46,1.18 r0 top
H7 "HOLE_R6_2D7MM" HOLE_R6_2D7MM 2283.46,1930.32 r0 top
H8 "HOLE_R6_2D7MM" HOLE_R6_2D7MM 5570.87,178.35 r0 top
HOLE2 "HOLE_2D7_6D0_A" HOLE_2D7_6D0_A 5181.89,102.76 r0 top
J2 "CON_TH1X2_2D54_STA_PZ" CON_TH1X2_2D54_STA_PZ 2204.72,3318.5 r90 top
J3 "BTB_SMD100_0D4_STA_FX" BTB_SMD100_0D4_STA_FX 4245.28,3293.31 r270 top
J4 "CON_TH1X4_2D54_SATA" CON_TH1X4_2D54_SATA 6010.24,2325.98 r270 top
J5 "CON_HDMI_TH_19P_STA" CON_HDMI_TH_19P_STA 764.57,30.32 r180 top
J6 "RJ45_LED_TH22_LIE" RJ45_LED_TH22_LIE 2551.18,548.43 r0 top
J7 "CONM_TH2X2_2D54_STA" CONM_TH2X2_2D54_STA 2234.25,1637.01 r90 top
J8 "SD_SM9_1D1_15D75" SD_SM9_1D1_15D75 5993.7,731.1 r0 top
J9 "FPC_15_1D0_LIE" FPC_15_1D0_LIE 86.61,820.87 r90 top
J10 "FPC_15_1D0_LIE" FPC_15_1D0_LIE 86.61,1661.42 r90 top
J11 "CON_TH20X2_2D54_STA" CON_TH20X2_2D54_STA 1143.7,1927.56 r0 top
J12 "EMMC_SLOT_30P_34P" EMMC_SLOT_30P_34P 2653.15,2470.47 r180 top
J13 "CON_USB2D0_TH1X2_LIE" CON_USB2D0_TH1X2_LIE 3522.83,168.11 r90 top
J14 "CON_SM2_1D25_STA" CON_SM2_1D25_STA 5926.38,1581.1 r270 top
J15 "TYPEC_SM24P_0D5" TYPEC_SM24P_0D5 4062.6,-76.38 r0 top
J16 "FPC_31P_0D3_LIE" FPC_31P_0D3_LIE 787.4,3332.68 r180 top
J17 "CONM_TH2X7_2D54_STA" CONM_TH2X7_2D54_STA 1775.59,2183.07 r0 top
J18 "CON_TH1X2_2D0_STA" CON_TH1X2_2D0_STA 1469.29,2411.42 r90 top
J19 "CON_TH1X2_2D0_STA" CON_TH1X2_2D0_STA 1811.02,2411.42 r90 top
J22 "CON_TH1X3_2D54_STA" CON_TH1X3_2D54_STA 5908.66,2737.8 r90 top
J23 "BAT_SM2_12X2" BAT_SM2_12X2 694.88,2361.81 r90 top
J24 "DC_TH5_12X10" DC_TH5_12X10 6159.45,3193.7 r90 top
J25 "AUDIO_SM6_LIE" AUDIO_SM6_LIE 4763.78,-46.46 r90 top
J30 "M2-M_KEY_SM_75_0D5" M2-M_KEY_SM_75_0D5 5184.25,3207.87 r0 top
L2 "L_6050" L_6050 5307.09,1826.77 r0 top
L15 "L_5020" L_5020 5244.09,1466.54 r180 top
L16 "CML_SM6_0D55_1" CML_SM6_0D55_1 2625.98,738.19 r0 top
L17 "CML_SM6_0D55_1" CML_SM6_0D55_1 2763.78,738.19 r0 top
L18 "CML_SM6_0D55_1" CML_SM6_0D55_1 2901.57,738.19 r0 top
L19 "CML_SM6_0D55_1" CML_SM6_0D55_1 3039.37,738.19 r0 top
L20 "L_3015" L_3015 1216.54,2964.57 r180 top
L21 "L_4020" L_4020 5224.41,2635.83 r0 top
L22 "L_2520" L_2520 1933.07,2627.95 r270 top
L23 "CML_SM4_0D6_1D5" CML_SM4_0D6_1D5 3673.23,622.05 r270 top
L24 "CML_SM4_0D6_1D5" CML_SM4_0D6_1D5 3527.56,622.05 r270 top
L29 "L_2520" L_2520 1761.81,2927.17 r180 top
L31 "CML_SM4_0D6_1D5" CML_SM4_0D6_1D5 4234.25,358.27 r90 top
LED2 "LED_D0603" LED_D0603 1224.02,-56.3 r0 top
LED3 "LED_D0603" LED_D0603 1422.83,-57.48 r0 top
M1 "MARK" MARK 6035.43,2486.22 r0 top
M2 "MARK" MARK 5990.16,-11.81 r0 top
M3 "MARK" MARK 224.41,-53.15 r0 top
M4 "MARK" MARK -1.97,3255.91 r0 top
P1 "TP_0R70" TP_0R70 5114.17,2027.56 r90 bottom
P4 "TP_0R70" TP_0R70 3019.68,2313.78 r180 bottom
P5 "TP_0R70" TP_0R70 2968.5,2335.43 r180 bottom
P6 "TP_0R70" TP_0R70 3017.72,2361.02 r270 bottom
P7 "TP_0R70" TP_0R70 2968.5,2382.68 r270 bottom
P8 "TP_0R70" TP_0R70 3019.68,2408.27 r180 bottom
P9 "TP_0R70" TP_0R70 2968.5,2429.92 r180 bottom
P10 "TP_0R70" TP_0R70 3019.68,2455.51 r180 bottom
P11 "TP_0R70" TP_0R70 2968.5,2477.17 r180 bottom
P12 "TP_0R70" TP_0R70 3865.35,3118.9 r180 bottom
P13 "TP_0R70" TP_0R70 3887.01,3071.65 r180 bottom
P14 "TP_0R70" TP_0R70 3301.18,1452.76 r180 bottom
P15 "TP_0R70" TP_0R70 3955.91,3118.9 r90 bottom
P16 "TP_0R70" TP_0R70 3934.25,3073.62 r180 bottom
P20 "TP_0R70" TP_0R70 3776.77,3342.91 r180 bottom
P24 "TP_0R70" TP_0R70 4312.99,2531.5 r180 bottom
P25 "TP_0R70" TP_0R70 4407.48,2517.72 r180 bottom
P26 "TP_0R70" TP_0R70 4354.33,2531.5 r180 bottom
P27 "TP_0R70" TP_0R70 4407.48,2557.09 r180 bottom
P28 "TP_0R70" TP_0R70 4596.46,2714.57 r0 top
Q1 "SOT_23" SOT_23 5248.03,2433.07 r0 top
Q2 "SOT_323" SOT_323 751.97,2822.83 r90 top
Q3 "SOT_323" SOT_323 751.97,2921.26 r90 top
Q12 "SOT_23" SOT_23 5271.65,1082.68 r180 top
Q13 "SOT_323" SOT_323 5328.74,1240.16 r180 top
Q14 "SOT_23" SOT_23 5433.07,1082.68 r180 top
Q15 "SOT_723" SOT_723 5486.22,1208.66 r180 top
Q16 "SOT_23" SOT_23 1326.77,2803.15 r0 top
Q17 "SOT_23" SOT_23 1190.94,2803.15 r0 top
Q18 "SOT_23" SOT_23 1055.12,2803.15 r0 top
Q19 "SOT_323" SOT_323 326.77,836.61 r90 top
Q20 "SOT_323" SOT_323 285.43,1169.29 r0 top
Q21 "SOT_23" SOT_23 5700.79,1651.57 r270 top
Q22 "SOT_23" SOT_23 2470.47,3155.51 r270 top
Q23 "SOT_23" SOT_23 2220.47,3149.61 r0 top
Q24 "SOT_23" SOT_23 1208.66,2277.56 r270 top
Q25 "SOT_323" SOT_323 1202.76,2122.05 r90 top
R1 "R0201" R0201 5346.46,2458.66 r180 top
R2 "R0201" R0201 5165.35,2399.61 r270 top
R3 "R0201" R0201 1960.63,2944.88 r0 top
R4 "R0201" R0201 1960.63,2980.32 r0 top
R5 "R0201" R0201 5265.75,2350.39 r0 top
R6 "R0201" R0201 5200.79,2350.39 r0 top
R7 "R0201" R0201 4946.85,2551.18 r0 top
R8 "R0201" R0201 651.57,2832.68 r90 top
R9 "R0201" R0201 828.74,2822.83 r270 top
R10 "R0201" R0201 679.13,2832.68 r90 top
R11 "R0201" R0201 651.57,2931.1 r90 top
R12 "R0201" R0201 828.74,2921.26 r270 top
R13 "R0201" R0201 679.13,2931.1 r270 top
R14 "R0201" R0201 5604.33,1688.98 r0 top
R15 "R0201" R0201 2641.73,3194.88 r270 top
R16 "R0201" R0201 169.29,2448.82 r90 top
R17 "FB1206" FB1206 5407.48,2399.61 r180 top
R18 "FB1206" FB1206 5708.66,1944.88 r0 top
R19 "R0201" R0201 4663.39,545.28 r270 top
R26 "R0201" R0201 5187.01,505.91 r180 top
R27 "R0201" R0201 5187.01,480.32 r180 top
R29 "R0201" R0201 5212.6,639.76 r180 top
R31 "FB0201" FB0201 5450.79,907.48 r0 top
R72 "R0201" R0201 3777.56,3350.39 r90 top
R109 "R0201" R0201 5212.6,614.17 r180 top
R115 "R0201" R0201 5271.65,2009.84 r270 top
R164 "R0402" R0402 5183.07,1055.12 r90 top
R175 "R0201" R0201 5379.92,2100.39 r0 top
R176 "R0201" R0201 5437.01,2470.47 r270 top
R177 "R0201" R0201 5344.49,2090.55 r90 top
R178 "R0201" R0201 5472.44,2531.5 r180 top
R179 "R0201" R0201 5427.17,2531.5 r0 top
R181 "R0201" R0201 5135.83,2051.18 r90 top
R182 "R0201" R0201 5145.67,2120.08 r180 top
R185 "R0201" R0201 5454.72,1584.65 r0 top
R187 "R0201" R0201 5535.43,1405.51 r180 top
R201 "R0201" R0201 5472.44,2505.91 r180 top
R202 "R0201" R0201 5535.43,1507.87 r0 top
R204 "R0201" R0201 5535.43,1482.28 r180 top
R205 "R0201" R0201 5535.43,1431.1 r0 top
R206 "R0201" R0201 5244.09,1165.35 r180 top
R208 "R0201" R0201 5318.9,1165.35 r0 top
R209 "R0201" R0201 5244.09,1216.54 r180 top
R210 "R0201" R0201 5244.09,1190.94 r0 top
R211 "R0201" R0201 228.35,460.63 r0 top
R212 "R0201" R0201 407.48,852.36 r270 top
R213 "R0201" R0201 5417.32,1173.23 r180 top
R214 "R0201" R0201 2590.55,1931.1 r0 top
R215 "R0201" R0201 2555.12,1940.94 r90 top
R216 "R0201" R0201 1257.87,9.84 r90 top
R217 "R0201" R0201 1283.46,9.84 r90 top
R218 "R0201" R0201 2244.09,2196.85 r0 top
R219 "R0201" R0201 1232.28,9.84 r270 top
R220 "R0201" R0201 2244.09,2248.03 r0 top
R221 "R0201" R0201 1206.69,9.84 r270 top
R222 "R0201" R0201 1309.06,9.84 r90 top
R223 "R0201" R0201 2244.09,2222.44 r0 top
R224 "R0201" R0201 1389.76,9.84 r270 top
R225 "R0201" R0201 1456.69,9.84 r90 top
R226 "R0201" R0201 1482.28,9.84 r90 top
R227 "R0201" R0201 1507.87,9.84 r90 top
R228 "R0201" R0201 5391.73,559.06 r0 top
R229 "R0201" R0201 1887.8,3076.77 r180 top
R230 "R0201" R0201 5417.32,1224.41 r0 top
R231 "R0201" R0201 5352.36,1084.65 r270 top
R232 "R0201" R0201 1407.48,2795.28 r90 top
R233 "R0201" R0201 1887.8,3051.18 r180 top
R234 "R0201" R0201 1417.32,2714.57 r180 top
R235 "R0201" R0201 1407.48,2750 r90 top
R236 "R0201" R0201 1338.58,3133.86 r180 top
R237 "R0201" R0201 2586.61,828.74 r90 top
R238 "R0201" R0201 2551.18,793.31 r0 top
R239 "R0201" R0201 2622.05,818.9 r180 top
R240 "R0201" R0201 1133.86,3175.2 r180 top
R241 "R0201" R0201 2561.02,828.74 r270 top
R242 "R0201" R0201 2622.05,844.49 r0 top
R243 "R0201" R0201 1279.53,2714.57 r0 top
R244 "R0603" R0603 1139.76,3250 r90 top
R245 "R0603" R0603 1192.91,3250 r90 top
R246 "R0201" R0201 1338.58,3159.45 r180 top
R247 "R0201" R0201 1124.02,3114.17 r90 top
R248 "R0201" R0201 2484.25,828.74 r90 top
R249 "R0201" R0201 1133.86,3149.61 r0 top
R250 "R0201" R0201 1822.83,3066.93 r90 top
R251 "R0201" R0201 1850.39,3066.93 r270 top
R252 "R0201" R0201 2484.25,881.89 r270 top
R253 "R0201" R0201 2509.84,828.74 r90 top
R254 "R0402" R0402 1438.98,2818.9 r90 top
R255 "R0201" R0201 1438.98,2877.95 r270 top
R256 "R0201" R0201 1551.18,2988.19 r90 top
R257 "R0201" R0201 1218.5,2685.04 r180 top
R258 "R0201" R0201 1590.55,2988.19 r90 top
R259 "R0201" R0201 1726.38,2998.03 r0 top
R260 "R0201" R0201 1773.62,2998.03 r0 top
R261 "R0201" R0201 1171.26,2712.6 r180 top
R262 "R0201" R0201 1027.56,2712.6 r180 top
R263 "R0201" R0201 100.39,2263.78 r180 top
R264 "R0201" R0201 226.38,935.04 r90 top
R265 "R0201" R0201 222.44,2458.66 r180 top
R266 "R0201" R0201 251.97,852.36 r270 top
R267 "R0201" R0201 374.02,1149.61 r90 top
R268 "R0201" R0201 374.02,1057.09 r270 top
R269 "R0201" R0201 348.43,1057.09 r270 top
R270 "R0201" R0201 348.43,1216.54 r90 top
R271 "R0201" R0201 301.18,1094.49 r180 top
R272 "R0201" R0201 348.43,1149.61 r90 top
R273 "R0201" R0201 1094.49,2112.2 r0 top
R274 "R0201" R0201 1094.49,2066.93 r0 top
R276 "R0201" R0201 4899.61,631.89 r0 top
R277 "R0201" R0201 3145.67,610.24 r90 top
R278 "R0201" R0201 5023.62,2535.43 r0 top
R279 "R0201" R0201 3135.83,675.2 r180 top
R280 "R0201" R0201 3135.83,647.64 r180 top
R281 "R0201" R0201 3362.2,673.23 r270 top
R282 "R0201" R0201 1816.93,523.62 r90 top
R283 "R0201" R0201 1836.61,523.62 r90 top
R284 "R0201" R0201 2029.53,2685.04 r90 top
R285 "R0201" R0201 4946.85,2730.32 r0 top
R286 "R0201" R0201 4708.66,517.72 r0 top
R287 "R0201" R0201 2133.86,2403.54 r180 top
R288 "R0201" R0201 4946.85,2525.59 r0 top
R289 "R0201" R0201 2133.86,2482.28 r180 top
R290 "R0201" R0201 4946.85,2679.13 r180 top
R291 "R0201" R0201 5263.78,531.5 r0 top
R293 "R0201" R0201 5066.93,2968.5 r90 top
R294 "R0201" R0201 5086.61,2968.5 r90 top
R295 "R0201" R0201 5167.32,2968.5 r270 top
R296 "R0201" R0201 5192.91,2968.5 r270 top
R297 "R0201" R0201 5218.5,2968.5 r270 top
R298 "R0201" R0201 4946.85,2576.77 r0 top
R299 "R0201" R0201 3663.39,622.05 r270 top
R300 "R0201" R0201 3517.72,622.05 r270 top
R301 "R0201" R0201 3683.07,622.05 r270 top
R302 "R0201" R0201 3537.4,622.05 r270 top
R303 "R0201" R0201 2151.57,2519.69 r90 top
R304 "R0201" R0201 5263.78,505.91 r180 top
R305 "R0201" R0201 5263.78,559.06 r0 top
R315 "R0201" R0201 2124.02,2519.69 r270 top
R316 "R0201" R0201 4708.66,492.13 r180 top
R317 "R0201" R0201 4830.71,517.72 r0 top
R318 "R0201" R0201 2068.9,2403.54 r180 top
R319 "R0201" R0201 5311.02,559.06 r0 top
R320 "R0201" R0201 2631.89,3159.45 r0 top
R321 "R0201" R0201 2381.89,3183.07 r90 top
R322 "R0201" R0201 2320.87,3192.91 r180 top
R323 "R0201" R0201 2320.87,3167.32 r180 top
R326 "R0201" R0201 5196.85,1216.54 r0 top
R327 "R0201" R0201 5196.85,1190.94 r0 top
R328 "R0201" R0201 1852.36,2858.27 r0 top
R329 "R0201" R0201 1470.47,2830.71 r270 top
R330 "R0201" R0201 1521.65,2830.71 r90 top
R331 "R0201" R0201 1732.28,2791.34 r180 top
R332 "R0201" R0201 1722.44,2830.71 r90 top
R333 "R0201" R0201 1078.74,2586.61 r180 top
R334 "R0201" R0201 1053.15,2527.56 r0 top
R335 "R0201" R0201 1053.15,2507.87 r0 top
R336 "R0201" R0201 1417.32,2645.67 r0 top
R337 "R0201" R0201 1417.32,2625.98 r0 top
R338 "R0201" R0201 4017.72,377.95 r180 top
R339 "R0201" R0201 3970.47,377.95 r0 top
R340 "R0201" R0201 4017.72,352.36 r0 top
R341 "R0201" R0201 3970.47,352.36 r180 top
R342 "R0402" R0402 1210.63,2190.94 r180 top
R343 "R0201" R0201 4244.09,358.27 r270 top
R344 "R0201" R0201 1094.49,2163.39 r0 top
R345 "R0201" R0201 4224.41,358.27 r270 top
R346 "R0201" R0201 4094.49,358.27 r270 top
R347 "R0201" R0201 4114.17,358.27 r270 top
R348 "R0201" R0201 4297.24,358.27 r270 top
R349 "R0201" R0201 4316.93,358.27 r270 top
R350 "R0201" R0201 1094.49,2137.8 r0 top
R351 "R0201" R0201 4318.9,716.54 r180 top
R352 "R0402" R0402 4470.47,340.55 r180 top
R353 "R0201" R0201 4468.5,442.91 r0 top
R354 "R0201" R0201 4484.25,570.87 r90 top
R355 "R0201" R0201 4458.66,570.87 r90 top
R356 "R0201" R0201 1332.68,2066.93 r180 top
R357 "R0201" R0201 1332.68,2096.46 r180 top
R358 "R0201" R0201 1287.4,2096.46 r0 top
R359 "R0201" R0201 1287.4,2066.93 r180 top
TP7 "TP_0R70" TP_0R70 5551.18,1980.32 r90 bottom
U10 "QFN12_0D5_2" QFN12_0D5_2 5251.97,2090.55 r270 top
U13 "SOT23_6" SOT23_6 5437.01,1482.28 r0 top
U18 "SON10_0D5_1" SON10_0D5_1 895.67,393.7 r0 top
U19 "SON10_0D5_1" SON10_0D5_1 777.56,393.7 r0 top
U20 "FPC_39P_0D3_LIE" FPC_39P_0D3_LIE 1889.76,3331.89 r90 top
U21 "DFN10_0D5_3" DFN10_0D5_3 1236.22,3114.17 r270 top
U22 "MSOP8_0D65_3" MSOP8_0D65_3 116.14,2500 r270 top
U25 "SOT23_5" SOT23_5 3246.06,645.67 r90 top
U26 "SOT23_5" SOT23_5 2041.34,2505.91 r180 top
U27 "QFN28_0D45_4" QFN28_0D45_4 5043.31,578.74 r270 top
U29 "SOT23_6" SOT23_6 5051.18,2627.95 r180 top
U30 "SOT23_5" SOT23_5 1620.08,2858.27 r90 top
U31 "MSOP8_0D65_5D0" MSOP8_0D65_5D0 1242.13,2545.28 r0 top
U32 "MSOP8_0D65_5D0" MSOP8_0D65_5D0 1598.43,2659.45 r0 top
U33 "BTB_SMD100X2_0D4_STA" BTB_SMD100X2_0D4_STA 3796.06,2292.91 r0 top
U34 "SON10_0D5_1" SON10_0D5_1 4133.86,277.56 r0 top
U35 "SON10_0D5_1" SON10_0D5_1 4336.61,277.56 r0 top
U36 "MLP14_0D5_2D5" MLP14_0D5_2D5 4299.21,635.83 r180 top
U37 "WLCSP12_0D4_1D5" WLCSP12_0D4_1D5 4490.16,480.32 r180 top
USB1 "USB_SM9_2D0_LIE" USB_SM9_2D0_LIE 1811.02,308.66 r0 top
Y1 "OSC_SM4_3D2X2D5" OSC_SM4_3D2X2D5 316.93,960.63 r0 top
Y3 "OSC_SM2_3D2X1D5" OSC_SM2_3D2X1D5 149.61,2594.49 r180 top

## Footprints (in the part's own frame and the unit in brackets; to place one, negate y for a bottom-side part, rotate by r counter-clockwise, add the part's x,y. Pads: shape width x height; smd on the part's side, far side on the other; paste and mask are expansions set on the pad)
AUDIO_SM6_LIE [mm]
  round 1.5 hole 1.5: 1(0,0) 8(7,0)
  oval 2x1.2 / inner oval 1.6x0.8 / far side oval 2x1.2 hole 0.686 slot 1.499 at 0 deg: 2(-0.2,2.05) 5(-0.2,-2.65)
  rect 1.3x2 smd: 3(6.8,3.55) 4(9.1,3.55) 6(3.1,-3.55) 7(8.6,-3.55)
  silkscreen extent -4.6,-3.2 9.6,3.2
BAT_SM2_12X2 [mm]
  rect 3.099x4.064 smd: 1(0,8.348) 2(0,-8.134)
  round 1.2 hole 1.2 unplated: 3(0,-3.685)
  round 1.3 hole 1.3 unplated: 4(0,3.815)
  silkscreen extent -6.99,-6.61 7.47,8.76
BTB_SMD100_0D4_STA_FX [mm]
  rect 1.14x0.2 smd: 1(0.09,-1.5) 2(2.73,-1.5) 3(0.09,-1.9) 4(2.73,-1.9) 5(0.09,-2.3) 6(2.73,-2.3) 7(0.09,-2.7) 8(2.73,-2.7) 9(0.09,-3.1) 10(2.73,-3.1) 11(0.09,-3.5) 12(2.73,-3.5) 13(0.09,-3.9) 14(2.73,-3.9) 15(0.09,-4.3) 16(2.73,-4.3) 17(0.09,-4.7) 18(2.73,-4.7) 19(0.09,-5.1) 20(2.73,-5.1) 21(0.09,-5.5) 22(2.73,-5.5) 23(0.09,-5.9) 24(2.73,-5.9) 25(0.09,-6.3) 26(2.73,-6.3) 27(0.09,-6.7) 28(2.73,-6.7) 29(0.09,-7.1) 30(2.73,-7.1) 31(0.09,-7.5) 32(2.73,-7.5) 33(0.09,-7.9) 34(2.73,-7.9) 35(0.09,-8.3) 36(2.73,-8.3) 37(0.09,-8.7) 38(2.73,-8.7) 39(0.09,-9.1) 40(2.73,-9.1) 41(0.09,-9.5) 42(2.73,-9.5) 43(0.09,-9.9) 44(2.73,-9.9) 45(0.09,-10.3) 46(2.73,-10.3) 47(0.09,-10.7) 48(2.73,-10.7) 49(0.09,-11.1) 50(2.73,-11.1) 51(0.09,-11.5) 52(2.73,-11.5) 53(0.09,-11.9) 54(2.73,-11.9) 55(0.09,-12.3) 56(2.73,-12.3) 57(0.09,-12.7) 58(2.73,-12.7) 59(0.09,-13.1) 60(2.73,-13.1) 61(0.09,-13.5) 62(2.73,-13.5) 63(0.09,-13.9) 64(2.73,-13.9) 65(0.09,-14.3) 66(2.73,-14.3) 67(0.09,-14.7) 68(2.73,-14.7) 69(0.09,-15.1) 70(2.73,-15.1) 71(0.09,-15.5) 72(2.73,-15.5) 73(0.09,-15.9) 74(2.73,-15.9) 75(0.09,-16.3) 76(2.73,-16.3) 77(0.09,-16.7) 78(2.73,-16.7) 79(0.09,-17.1) 80(2.73,-17.1) 81(0.09,-17.5) 82(2.73,-17.5) 83(0.09,-17.9) 84(2.73,-17.9) 85(0.09,-18.3) 86(2.73,-18.3) 87(0.09,-18.7) 88(2.73,-18.7) 89(0.09,-19.1) 90(2.73,-19.1) 91(0.09,-19.5) 92(2.73,-19.5) 93(0.09,-19.9) 94(2.73,-19.9) 95(0.09,-20.3) 96(2.73,-20.3) 97(0.09,-20.7) 98(2.73,-20.7) 99(0.09,-21.1) 100(2.73,-21.1)
  silkscreen extent 0,-22.54 2.84,0.01
BTB_SMD100X2_0D4_STA [mm]
  rect 1.14x0.2 smd: 1(18.39,-7.32) 2(15.73,-7.32) 3(18.39,-6.92) 4(15.73,-6.92) 5(18.39,-6.52) 6(15.73,-6.52) 7(18.39,-6.12) 8(15.73,-6.12) 9(18.39,-5.72) 10(15.73,-5.72) 11(18.39,-5.32) 12(15.73,-5.32) 13(18.39,-4.92) 14(15.73,-4.92) 15(18.39,-4.52) 16(15.73,-4.52) 17(18.39,-4.12) 18(15.73,-4.12) 19(18.39,-3.72) 20(15.73,-3.72) 21(18.39,-3.32) 22(15.73,-3.32) 23(18.39,-2.92) 24(15.73,-2.92) 25(18.39,-2.52) 26(15.73,-2.52) 27(18.39,-2.12) 28(15.73,-2.12) 29(18.39,-1.72) 30(15.73,-1.72) 31(18.39,-1.32) 32(15.73,-1.32) 33(18.39,-0.92) 34(15.73,-0.92) 35(18.39,-0.52) 36(15.73,-0.52) 37(18.39,-0.12) 38(15.73,-0.12) 39(18.39,0.28) 40(15.73,0.28) 41(18.39,0.68) 42(15.73,0.68) 43(18.39,1.08) 44(15.73,1.08) 45(18.39,1.48) 46(15.73,1.48) 47(18.39,1.88) 48(15.73,1.88) 49(18.39,2.28) 50(15.73,2.28) 51(18.39,2.68) 52(15.73,2.68) 53(18.39,3.08) 54(15.73,3.08) 55(18.39,3.48) 56(15.73,3.48) 57(18.39,3.88) 58(15.73,3.88) 59(18.39,4.28) 60(15.73,4.28) 61(18.39,4.68) 62(15.73,4.68) 63(18.39,5.08) 64(15.73,5.08) 65(18.39,5.48) 66(15.73,5.48) 67(18.39,5.88) 68(15.73,5.88) 69(18.39,6.28) 70(15.73,6.28) 71(18.39,6.68) 72(15.73,6.68) 73(18.39,7.08) 74(15.73,7.08) 75(18.39,7.48) 76(15.73,7.48) 77(18.39,7.88) 78(15.73,7.88) 79(18.39,8.28) 80(15.73,8.28) 81(18.39,8.68) 82(15.73,8.68) 83(18.39,9.08) 84(15.73,9.08) 85(18.39,9.48) 86(15.73,9.48) 87(18.39,9.88) 88(15.73,9.88) 89(18.39,10.28) 90(15.73,10.28) 91(18.39,10.68) 92(15.73,10.68) 93(18.39,11.08) 94(15.73,11.08) 95(18.39,11.48) 96(15.73,11.48) 97(18.39,11.88) 98(15.73,11.88) 99(18.39,12.28) 100(15.73,12.28) 101(-15.68,-7.32) 102(-18.32,-7.32) 103(-15.68,-6.92) 104(-18.32,-6.92) 105(-15.68,-6.52) 106(-18.32,-6.52) 107(-15.68,-6.12) 108(-18.32,-6.12) 109(-15.68,-5.72) 110(-18.32,-5.72) 111(-15.68,-5.32) 112(-18.32,-5.32) 113(-15.68,-4.92) 114(-18.32,-4.92) 115(-15.68,-4.52) 116(-18.32,-4.52) 117(-15.68,-4.12) 118(-18.32,-4.12) 119(-15.68,-3.72) 120(-18.32,-3.72) 121(-15.68,-3.32) 122(-18.32,-3.32) 123(-15.68,-2.92) 124(-18.32,-2.92) 125(-15.68,-2.52) 126(-18.32,-2.52) 127(-15.68,-2.12) 128(-18.32,-2.12) 129(-15.68,-1.72) 130(-18.32,-1.72) 131(-15.68,-1.32) 132(-18.32,-1.32) 133(-15.68,-0.92) 134(-18.32,-0.92) 135(-15.68,-0.52) 136(-18.32,-0.52) 137(-15.68,-0.12) 138(-18.32,-0.12) 139(-15.68,0.28) 140(-18.32,0.28) 141(-15.68,0.68) 142(-18.32,0.68) 143(-15.68,1.08) 144(-18.32,1.08) 145(-15.68,1.48) 146(-18.32,1.48) 147(-15.68,1.88) 148(-18.32,1.88) 149(-15.68,2.28) 150(-18.32,2.28) 151(-15.68,2.68) 152(-18.32,2.68) 153(-15.68,3.08) 154(-18.32,3.08) 155(-15.68,3.48) 156(-18.32,3.48) 157(-15.68,3.88) 158(-18.32,3.88) 159(-15.68,4.28) 160(-18.32,4.28) 161(-15.68,4.68) 162(-18.32,4.68) 163(-15.68,5.08) 164(-18.32,5.08) 165(-15.68,5.48) 166(-18.32,5.48) 167(-15.68,5.88) 168(-18.32,5.88) 169(-15.68,6.28) 170(-18.32,6.28) 171(-15.68,6.68) 172(-18.32,6.68) 173(-15.68,7.08) 174(-18.32,7.08) 175(-15.68,7.48) 176(-18.32,7.48) 177(-15.68,7.88) 178(-18.32,7.88) 179(-15.68,8.28) 180(-18.32,8.28) 181(-15.68,8.68) 182(-18.32,8.68) 183(-15.68,9.08) 184(-18.32,9.08) 185(-15.68,9.48) 186(-18.32,9.48) 187(-15.68,9.88) 188(-18.32,9.88) 189(-15.68,10.28) 190(-18.32,10.28) 191(-15.68,10.68) 192(-18.32,10.68) 193(-15.68,11.08) 194(-18.32,11.08) 195(-15.68,11.48) 196(-18.32,11.48) 197(-15.68,11.88) 198(-18.32,11.88) 199(-15.68,12.28) 200(-18.32,12.28)
  round 6 / inner round 3 / far side round 6 hole 2.6: 201(16.51,-23.98) 202(-16.49,-23.98) 203(-16.51,23.97) 204(16.49,23.97)
  silkscreen extent -19.99,-27.48 20.03,27.5
C0201 [mm]
  rect 0.3x0.3 smd: 1(-0.25,0) 2(0.25,0)
  silkscreen extent -0.5,-0.25 0.5,0.25
C0402 [mm]
  rect 0.5x0.5 smd: 1(-0.4,0) 2(0.4,0)
  silkscreen extent -0.8,-0.4 0.8,0.4
C0603 [mm]
  rect 0.7x0.9 smd: 1(-0.7,0) 2(0.7,0)
  silkscreen extent -1.2,-0.6 1.2,0.6
C0805 [mm]
  rect 0.9x1.3 smd: 1(-0.85,0) 2(0.85,0)
  silkscreen extent -1.5,-0.8 1.5,0.8
CML_SM4_0D6_1D5 [mm]
  rect 0.5x0.3 smd: 1(-0.625,-0.275) 2(-0.625,0.275) 3(0.625,0.275) 4(0.625,-0.275)
  silkscreen extent -1,-0.6 1.03,0.6
CML_SM6_0D55_1 [mm]
  rect 0.6x0.4 smd: 1(1.48,0.01) 2(1.48,-0.54) 3(0,0) 4(0,-0.55)
  rect 0.5x0.4 smd: 5(0.74,0.2) 6(0.74,-0.74)
  silkscreen extent 0.14,-0.76 1.5,0.21
CON_HDMI_TH_19P_STA [mil]
  rect 11.81x102.36 smd: 1(-180,-177.5) 2(-160.31,-177.5) 3(-140.63,-177.5) 4(-120.94,-177.5) 5(-101.26,-177.5) 6(-81.57,-177.5) 7(-61.89,-177.5) 8(-42.2,-177.5) 9(-22.52,-177.5) 10(-2.83,-177.5) 11(16.85,-177.5) 12(36.54,-177.5) 13(56.22,-177.5) 14(75.91,-177.5) 15(95.59,-177.5) 16(115.28,-177.5) 17(134.96,-177.5) 18(154.65,-177.5) 19(174.33,-177.5)
  oval 59.06x137.8 hole 35 slot 106 at 90 deg: 20(282.6,-147.58) 21(-288.27,-147.58)
  oval 59.06x98.43 hole 35 slot 66 at 90 deg: 22(-288.27,87.07) 23(282.6,87.07)
  silkscreen extent -287,-178 283,284
CON_SM2_1D25_STA [mm]
  rect 0.8x1.6 smd: 1(-1.25,0) 2(0,0)
  rect 2.1x3 smd: 3(-3.85,2.82) 4(2.6,2.82)
  silkscreen extent -5,-1.65 3.72,4.47
CON_TH1X2_2D0_STA [mm]
  rect 1.3x1.3 hole 0.8 mask+0.075: 1(0,0)
  round 1.3 hole 0.8 mask+0.075: 2(0,-2)
CON_TH1X2_2D54_STA_PZ [mm]
  rect 1.3x1.3 / inner rect 1.5x1.5 / far side rect 1.5x1.5 hole 0.9 mask+0.1: 1(0,0)
  round 1.3 / inner round 1.5 / far side round 1.5 hole 0.9 mask+0.1: 2(0,-2.54)
  silkscreen extent -1.25,-3.79 1.25,1.25
CON_TH1X3_2D54_STA [mm]
  round 1.3 / inner round 1.3 / far side round 1.6 hole 1: 1(-2.54,0) 2(0,0) 3(2.54,0)
  silkscreen extent -3.81,-1.9 3.81,1.27
CON_TH1X4_2D54_SATA [mm]
  round 1.4 hole 0.9: 1(0.01,0) 2(2.55,0) 3(5.09,0) 4(7.63,0)
  silkscreen extent -1.19,-3.3 8.81,2.36
CON_TH20X2_2D54_STA [mm]
  round 1.7 / inner round 1.4 / far side round 1.7 hole 1.1: 1(-24.13,-1.27) 2(-24.13,1.27) 3(-21.59,-1.27) 4(-21.59,1.27) 5(-19.05,-1.27) 6(-19.05,1.27) 7(-16.51,-1.27) 8(-16.51,1.27) 9(-13.97,-1.27) 10(-13.97,1.27) 11(-11.43,-1.27) 12(-11.43,1.27) 13(-8.89,-1.27) 14(-8.89,1.27) 15(-6.35,-1.27) 16(-6.35,1.27) 17(-3.81,-1.27) 18(-3.81,1.27) 19(-1.27,-1.27) 20(-1.27,1.27) 21(1.27,-1.27) 22(1.27,1.27) 23(3.81,-1.27) 24(3.81,1.27) 25(6.35,-1.27) 26(6.35,1.27) 27(8.89,-1.27) 28(8.89,1.27) 29(11.43,-1.27) 30(11.43,1.27) 31(13.97,-1.27) 32(13.97,1.27) 33(16.51,-1.27) 34(16.51,1.27) 35(19.05,-1.27) 36(19.05,1.27) 37(21.59,-1.27) 38(21.59,1.27) 39(24.13,-1.27) 40(24.13,1.27)
  silkscreen extent -26.35,-3.84 25.43,2.54
CON_USB2D0_TH1X2_LIE [mm]
  round 1.3 / inner round 1.1 / far side round 1.3 hole 0.9: 1(3.18,3.5) 2(3.18,1) 3(3.18,-1) 4(3.18,-3.5) 5(5.68,3.5) 6(5.68,1) 7(5.68,-1) 8(5.68,-3.5)
  round 2.8 / inner round 2.8 / far side round 3.05 hole 2.3: 9(0,6.7) 10(0,-6.7) 11(5.7,6.7) 12(5.7,-6.7)
  silkscreen extent -9.97,-7.52 7.1,7.61
CONM_TH2X2_2D54_STA [mil]
  round 63 / inner round 50 / far side round 63 hole 35 mask+2: 1(100,-100) 2(100,0) 3(0,-100)
  rect 63x63 hole 35 mask+2: 4(0,0)
  silkscreen extent -50,-150 150,50
CONM_TH2X7_2D54_STA [mil]
  round 60 / inner round 45.28 / far side round 60 hole 35.43 mask+1.99: 1(-300,-50.39) 2(-300,49.61) 3(-200,-50.39) 4(-200,49.61) 5(-100,-50.39) 6(-100,49.61) 7(0,-50.39) 8(0,49.61) 9(100,-50.39) 10(100,49.61) 11(200,-50.39) 12(200,49.61) 13(300,-50.39) 14(300,49.61)
  silkscreen extent -351,-100 352,100
DC_TH5_12X10 [mm]
  oval 1.2x2.5 / inner oval 1.2x2.5 / far side oval 1.5x2.8 hole 0.787 slot 1.981 at 90 deg: 1(3.2,10.2) 2(-5.3,10.2) 3(0,10.2)
  oval 1x2.5 / inner oval 1x2.5 / far side oval 1.2x2.8 hole 0.584 slot 1.981 at 90 deg: 4(-6.2,3) 5(3.6,3)
  Top keep-out region: -0.759,4.741 0.741,4.741 0.741,3.241 -0.759,3.241 -0.759,4.741
  silkscreen extent -6.3,0 4.5,11.6
DFN10_0D5_3 [mm]
  rect 0.3x0.55 smd: 1(-1,-1.34) 2(-0.5,-1.34) 3(0,-1.34) 4(0.5,-1.34) 5(1,-1.34) 6(1,1.35) 7(0.5,1.35) 8(0,1.35) 9(-0.5,1.35) 10(-1,1.35)
  rect 2.6x1.75 smd: 11(0,0)
  silkscreen extent -1.48,-1.98 1.48,1.52
DO_214AC [mm]
  rect 2.5x2 smd mask+0.05: 1(-2,0) 2(2,0)
  silkscreen extent -3.54,-1.65 3.68,1.65
EMMC_SLOT_30P_34P [mm]
  rect 0.23x0.7 smd: 1(0,0) 2(0.4,0) 3(0.8,0) 4(1.2,0) 5(1.6,0) 6(2,0) 7(2.4,0) 8(2.8,0) 9(3.2,0) 10(3.6,0) 11(4,0) 12(4.4,0) 13(4.8,0) 14(5.2,0) 15(5.6,0) 16(6,0) 17(6.4,0) 18(6.4,2.5) 19(6,2.5) 20(5.6,2.5) 21(5.2,2.5) 22(4.8,2.5) 23(4.4,2.5) 24(4,2.5) 25(3.6,2.5) 26(3.2,2.5) 27(2.8,2.5) 28(2.4,2.5) 29(2,2.5) 30(1.6,2.5) 31(1.2,2.5) 32(0.8,2.5) 33(0.4,2.5) 34(0,2.5) 35(0.4,-13) 36(0.8,-13) 37(1.2,-13) 38(1.6,-13) 39(2,-13) 40(2.4,-13) 41(2.8,-13) 42(3.2,-13) 43(3.6,-13) 44(4,-13) 45(4.4,-13) 46(4.8,-13) 47(5.2,-13) 48(5.6,-13) 49(6,-13) 50(6,-10.5) 51(5.6,-10.5) 52(5.2,-10.5) 53(4.8,-10.5) 54(4.4,-10.5) 55(4,-10.5) 56(3.6,-10.5) 57(3.2,-10.5) 58(2.8,-10.5) 59(2.4,-10.5) 60(2,-10.5) 61(1.6,-10.5) 62(1.2,-10.5) 63(0.8,-10.5) 64(0.4,-10.5)
  silkscreen extent -3.47,-14.1 10.03,4.4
